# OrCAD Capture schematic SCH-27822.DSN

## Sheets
1 1. Title Page: title: FRDM-KL46Z; rev: B1; company: Freescale Semiconductor; note: SCH-27822 | PDF: SPF-27822; note: 6501 William Cannon Drive West; note: Austin, TX 78735-8598
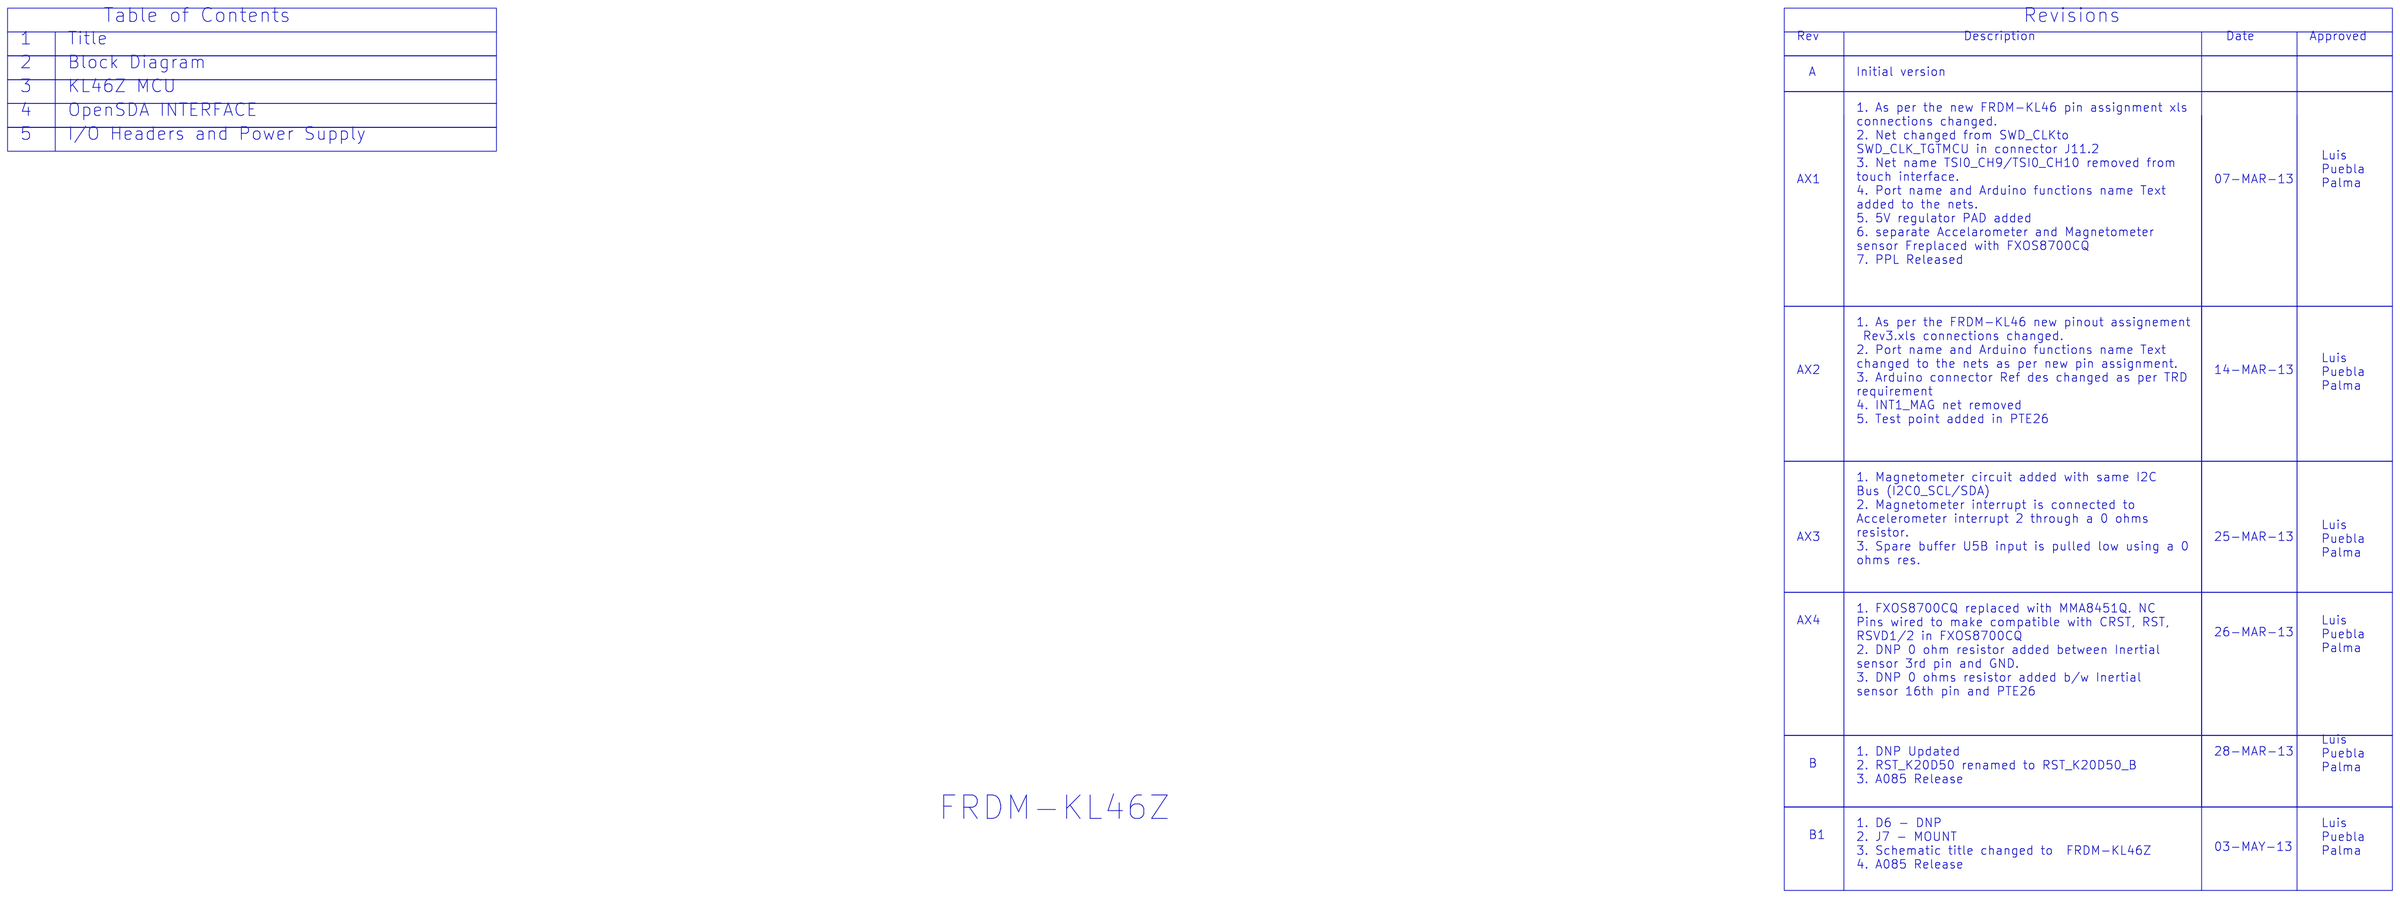
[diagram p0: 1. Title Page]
2 2. Block Diagram
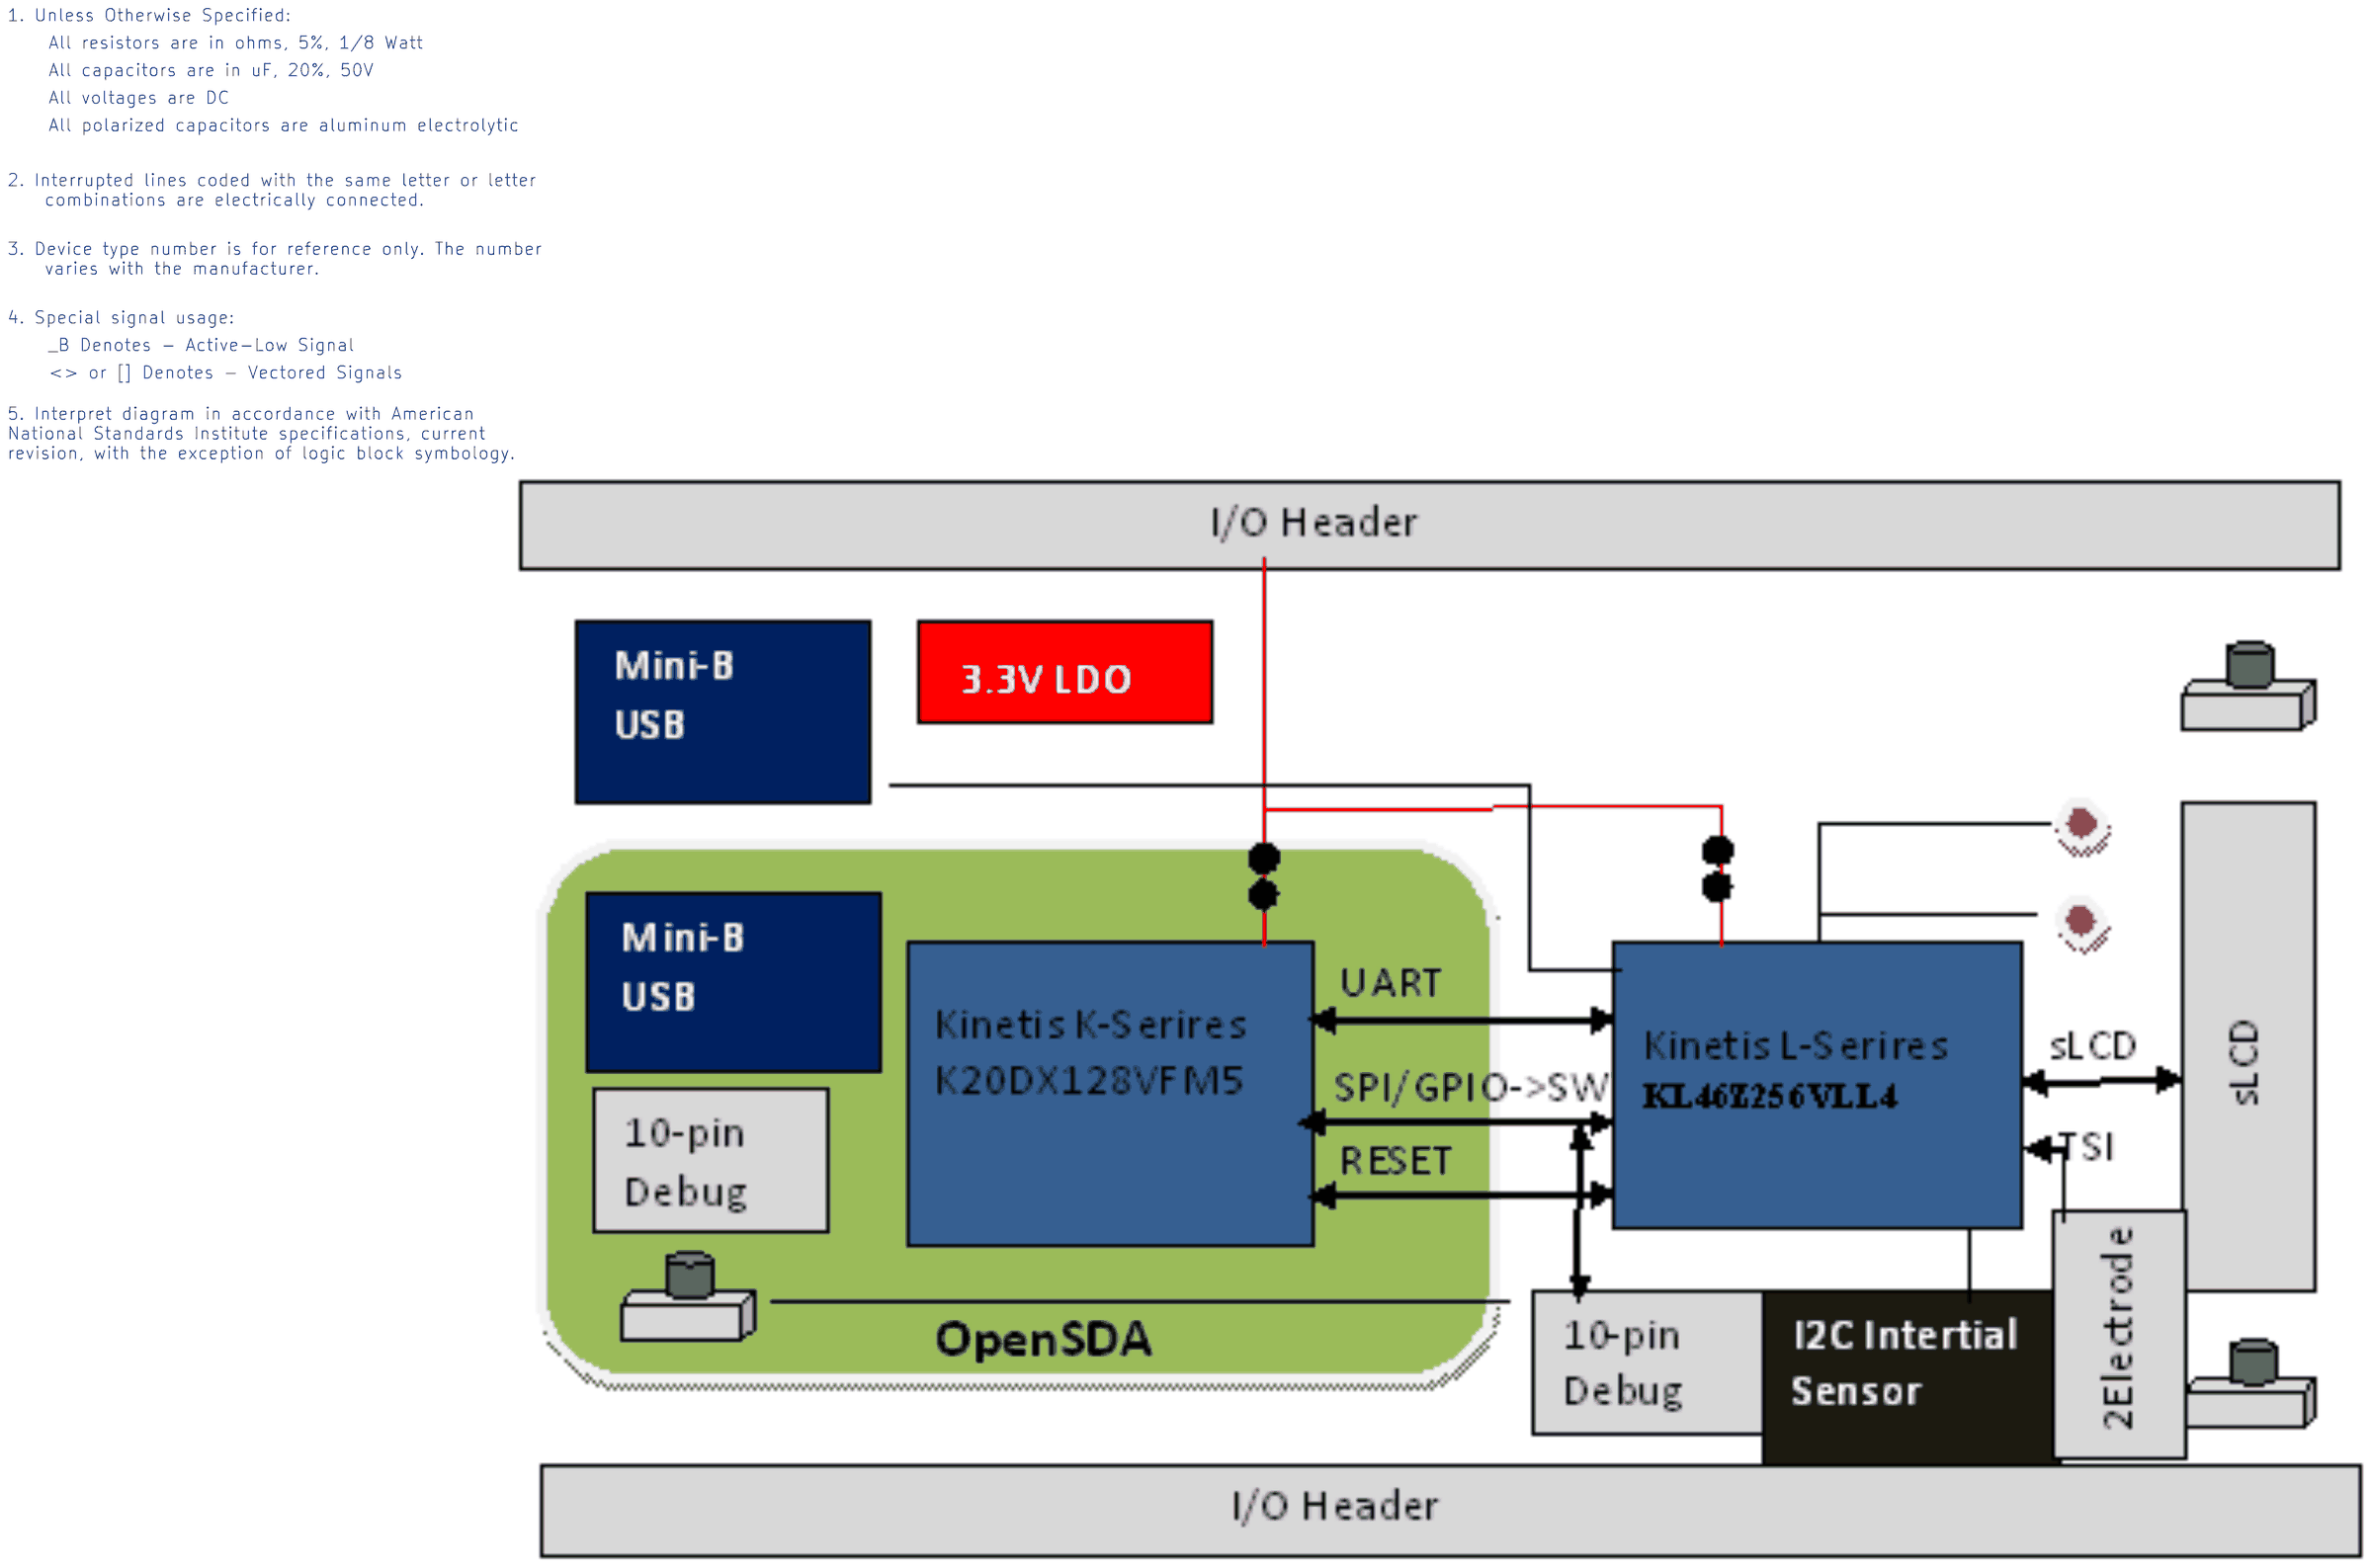
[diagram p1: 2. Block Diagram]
3 3. KL46Z MCU: size C
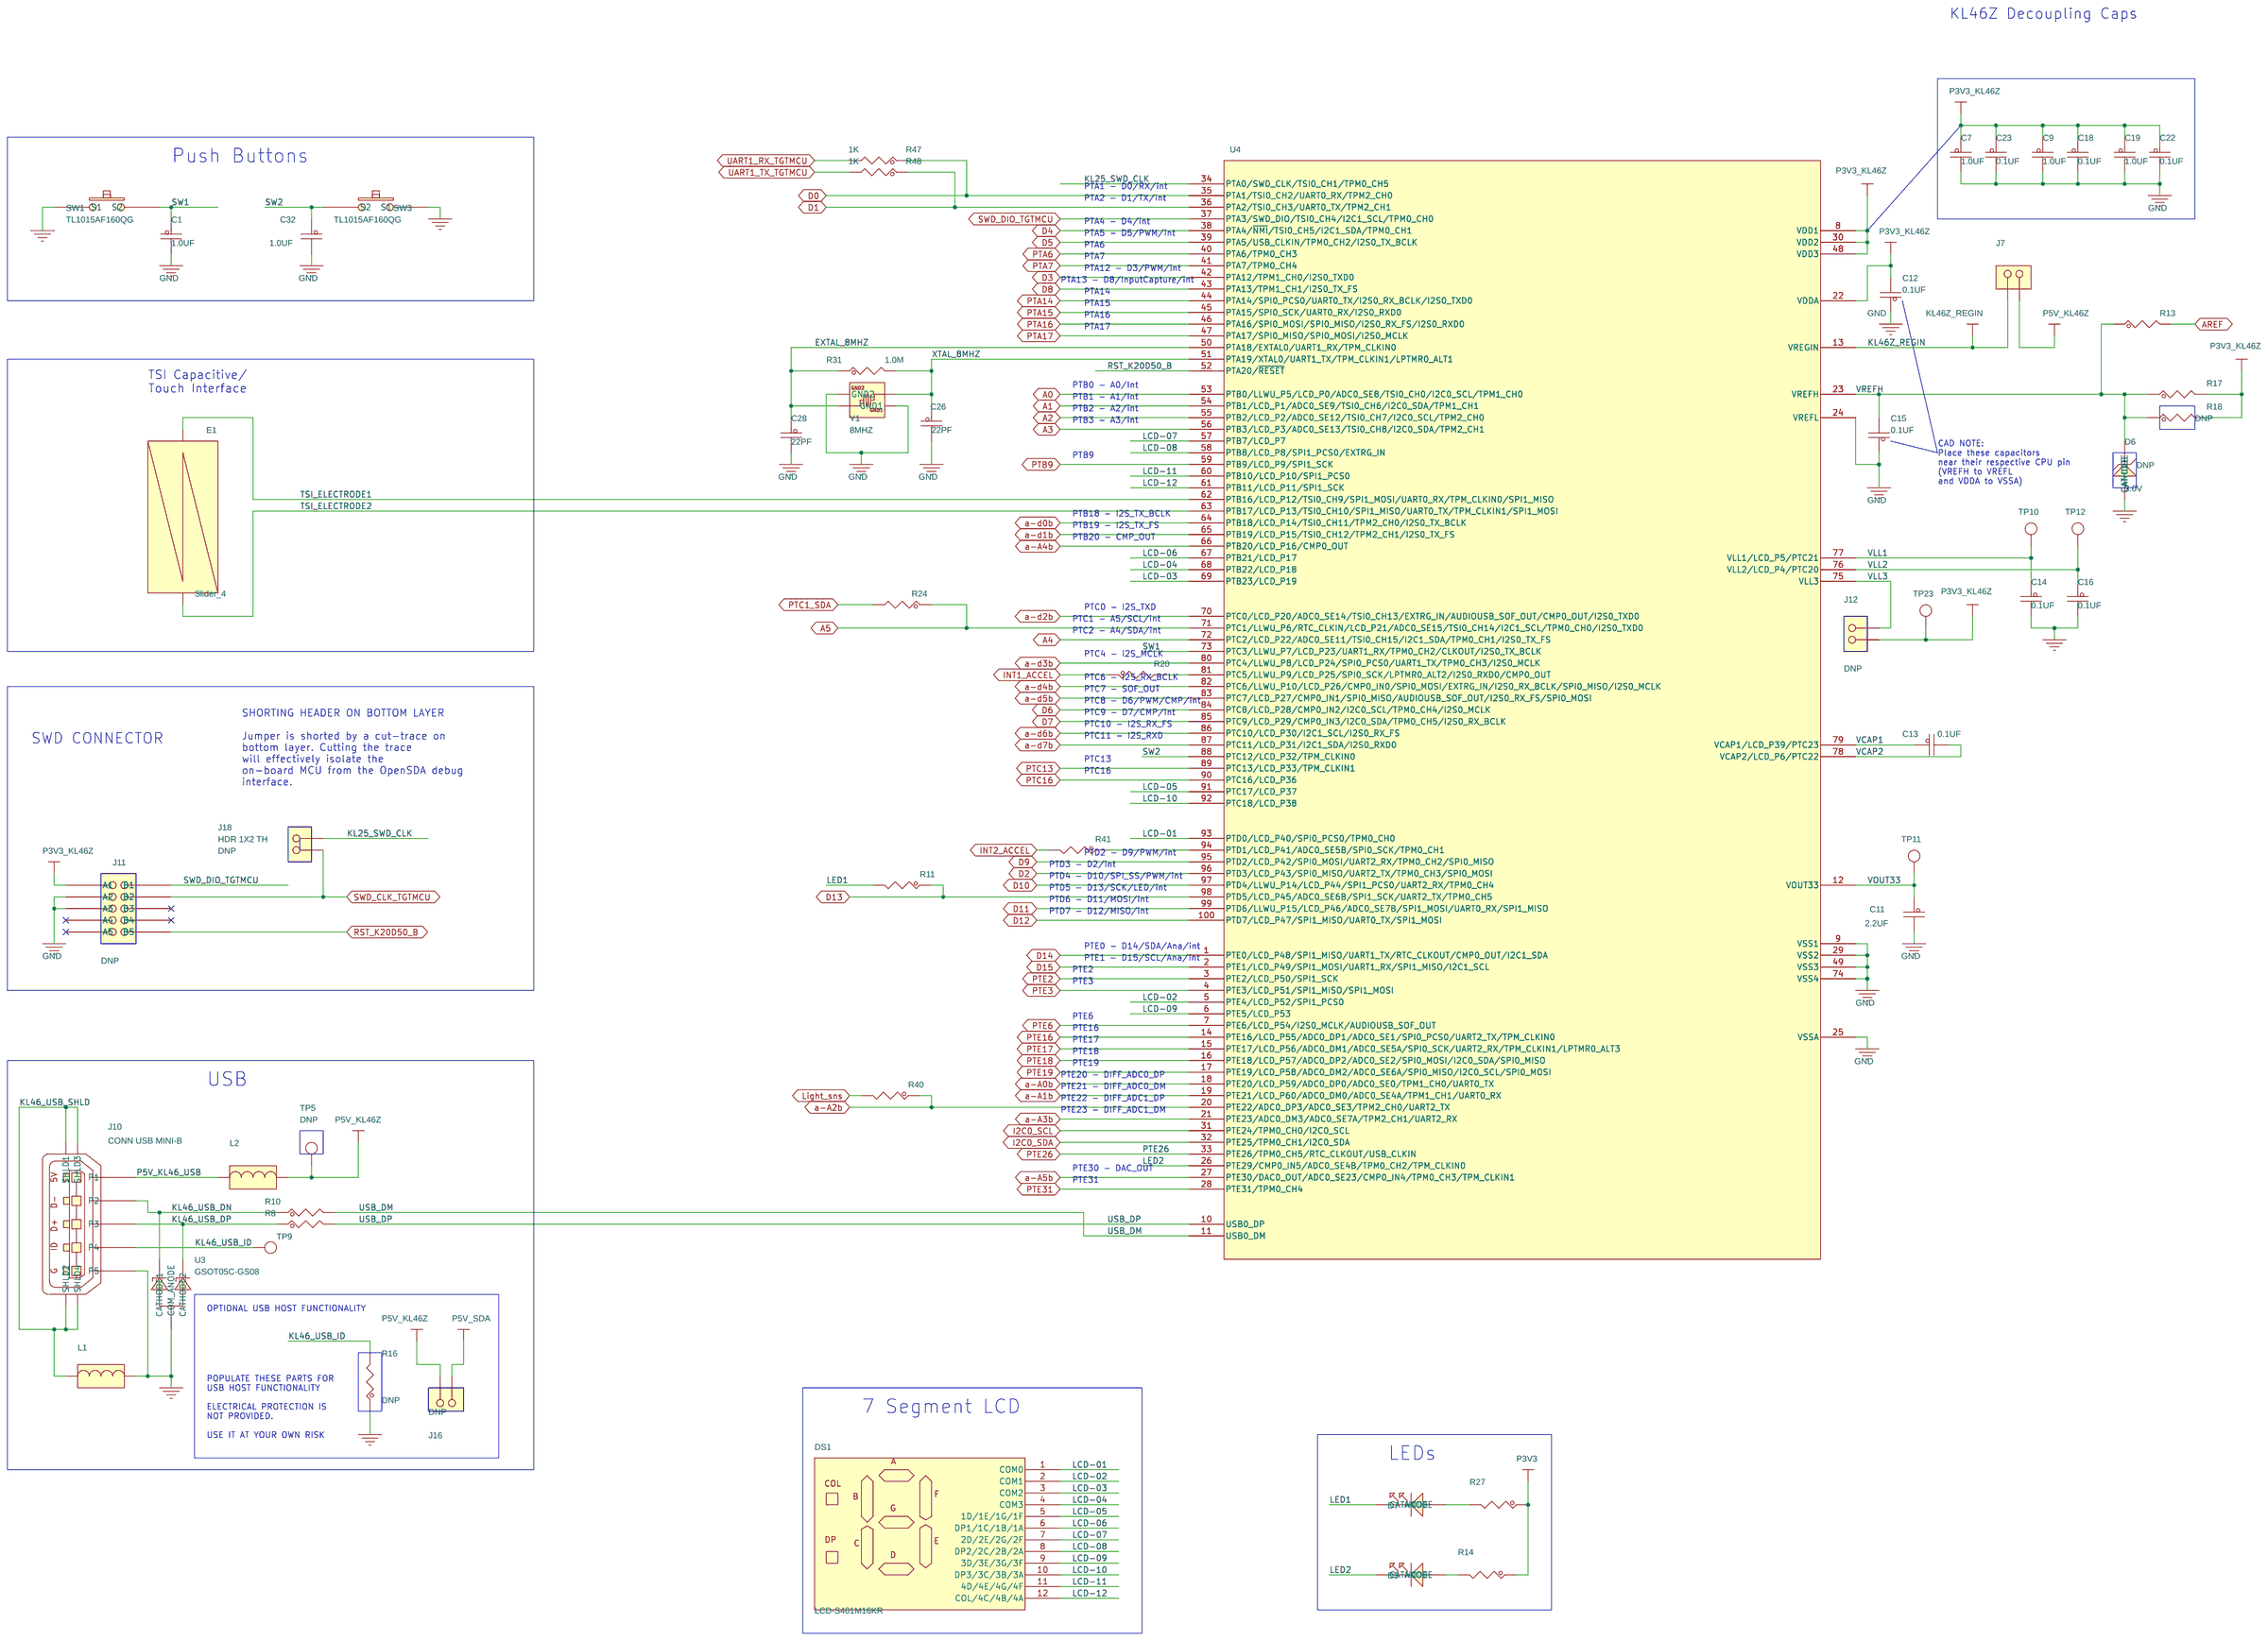
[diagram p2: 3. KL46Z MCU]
4 4. OpenSDA interface: size C
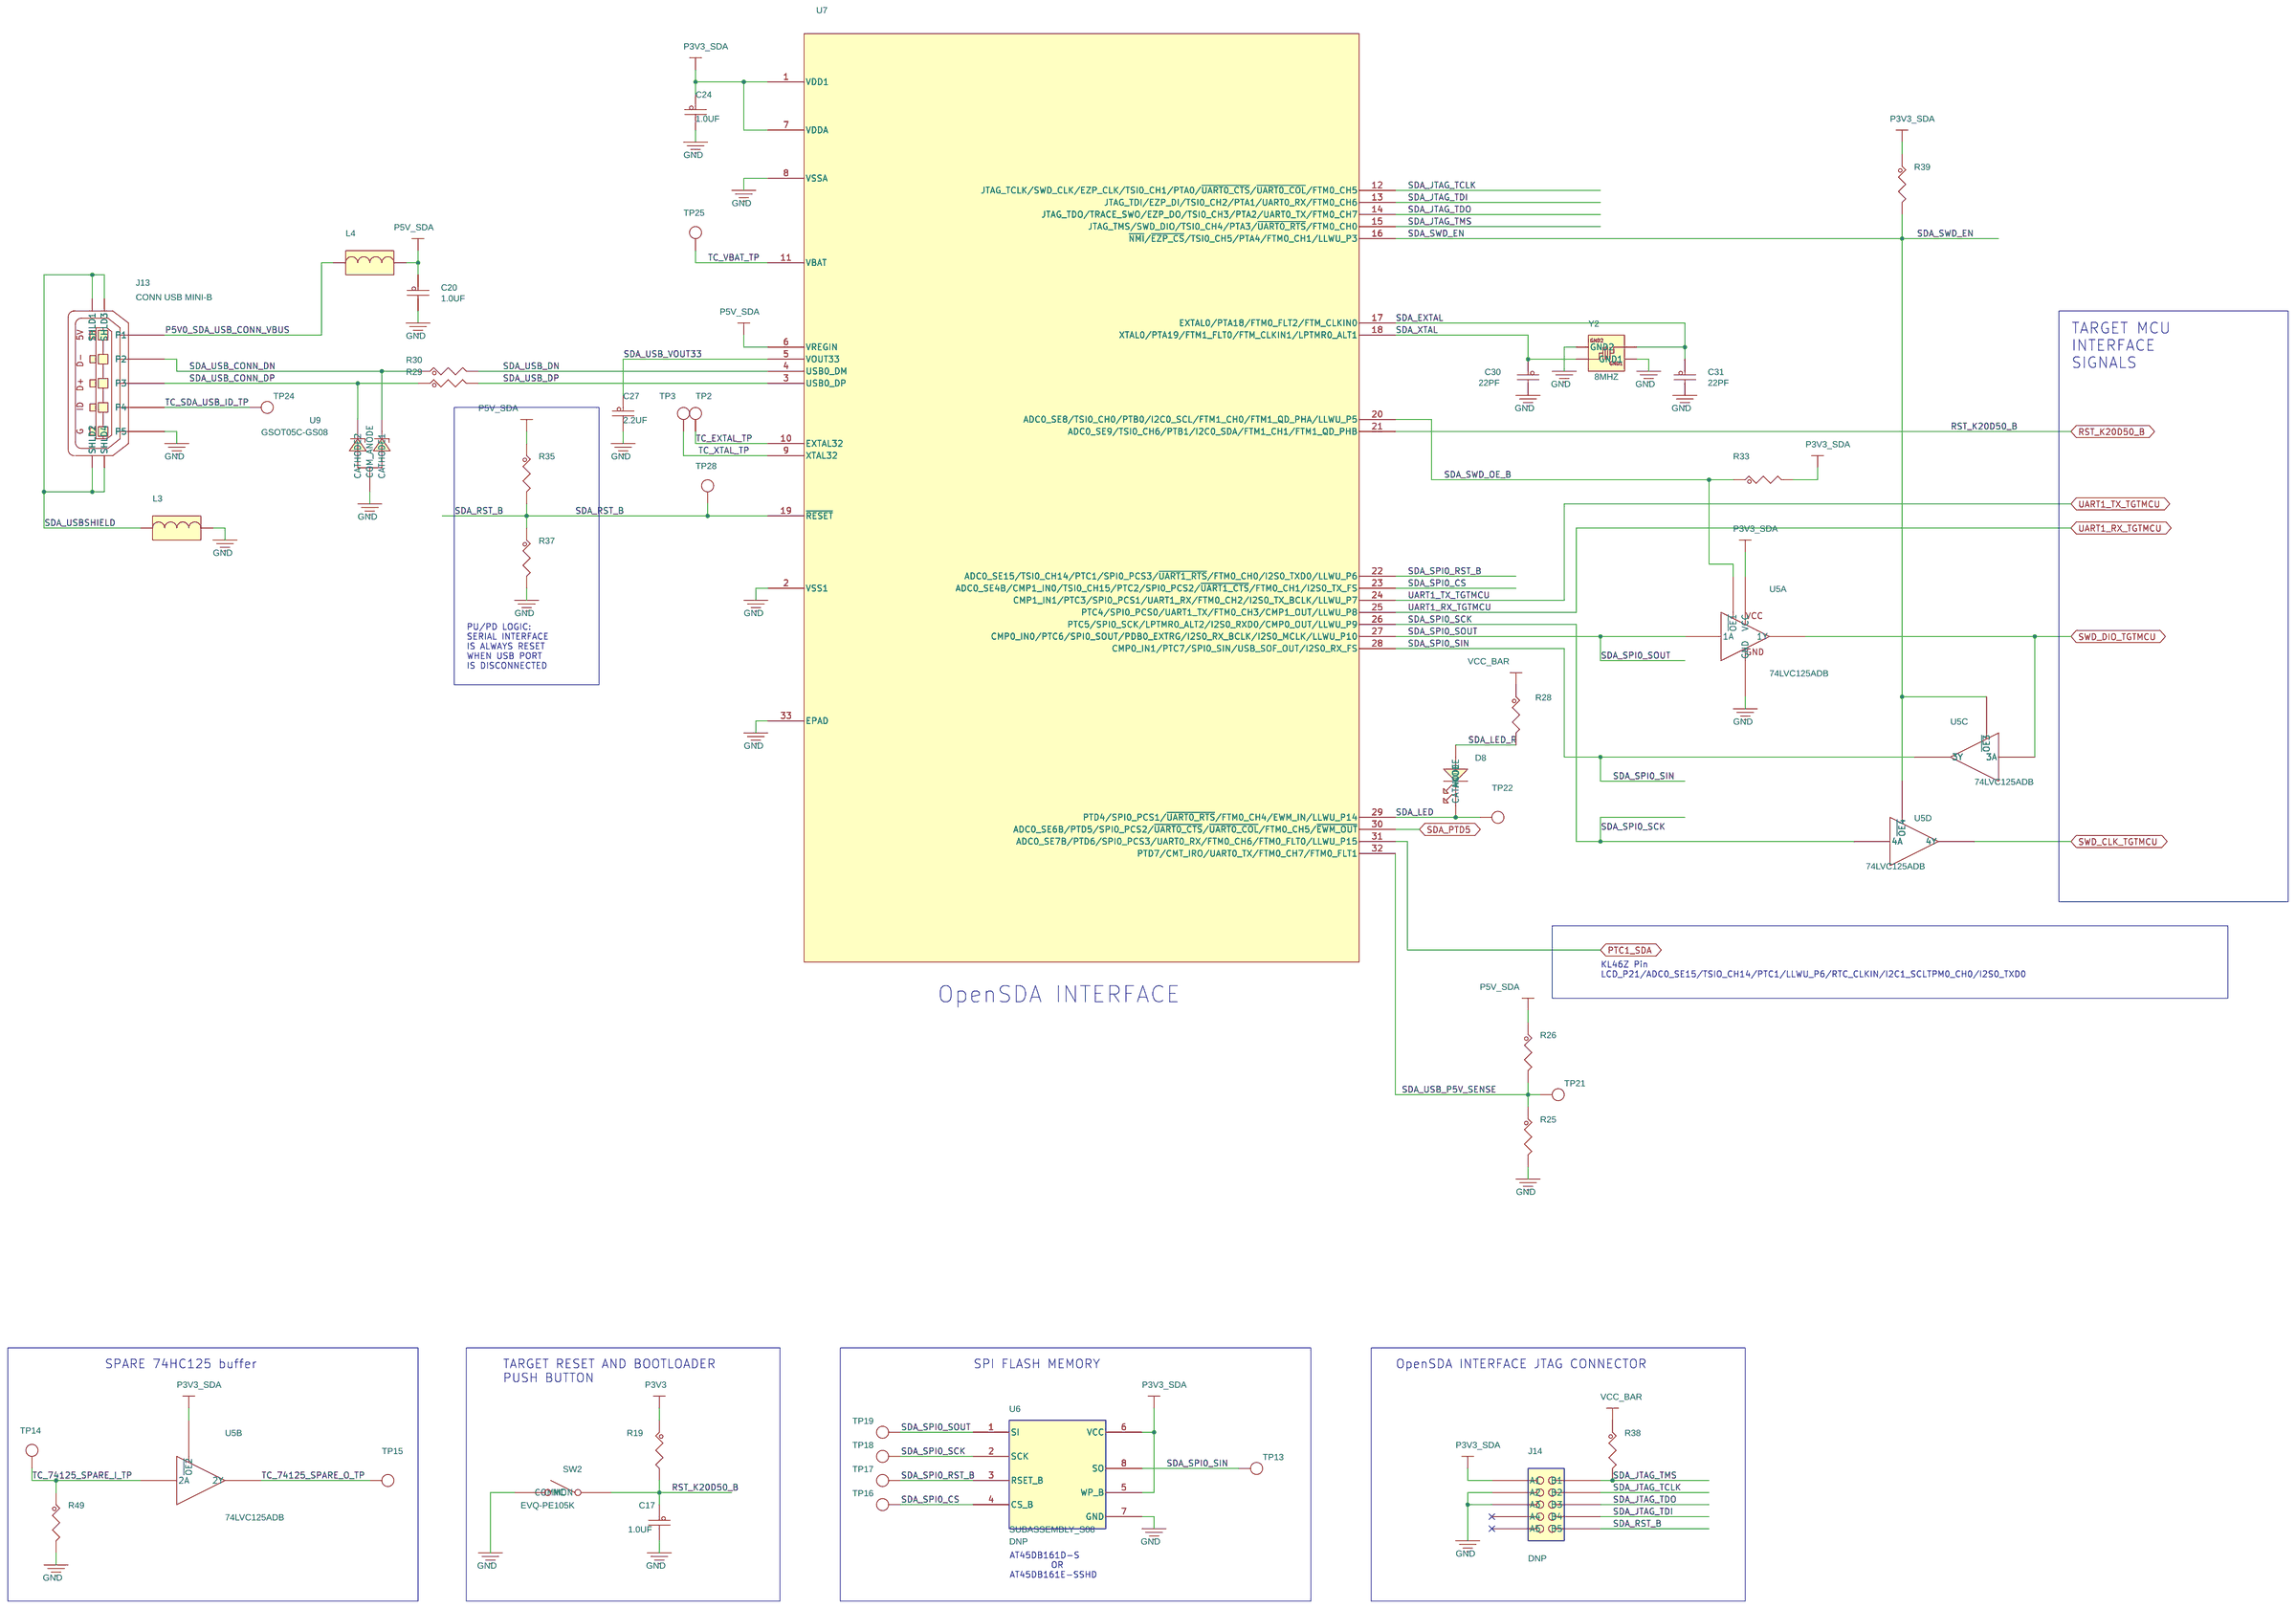
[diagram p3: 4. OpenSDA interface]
5 5. I/O Headers and Power Supply: size C
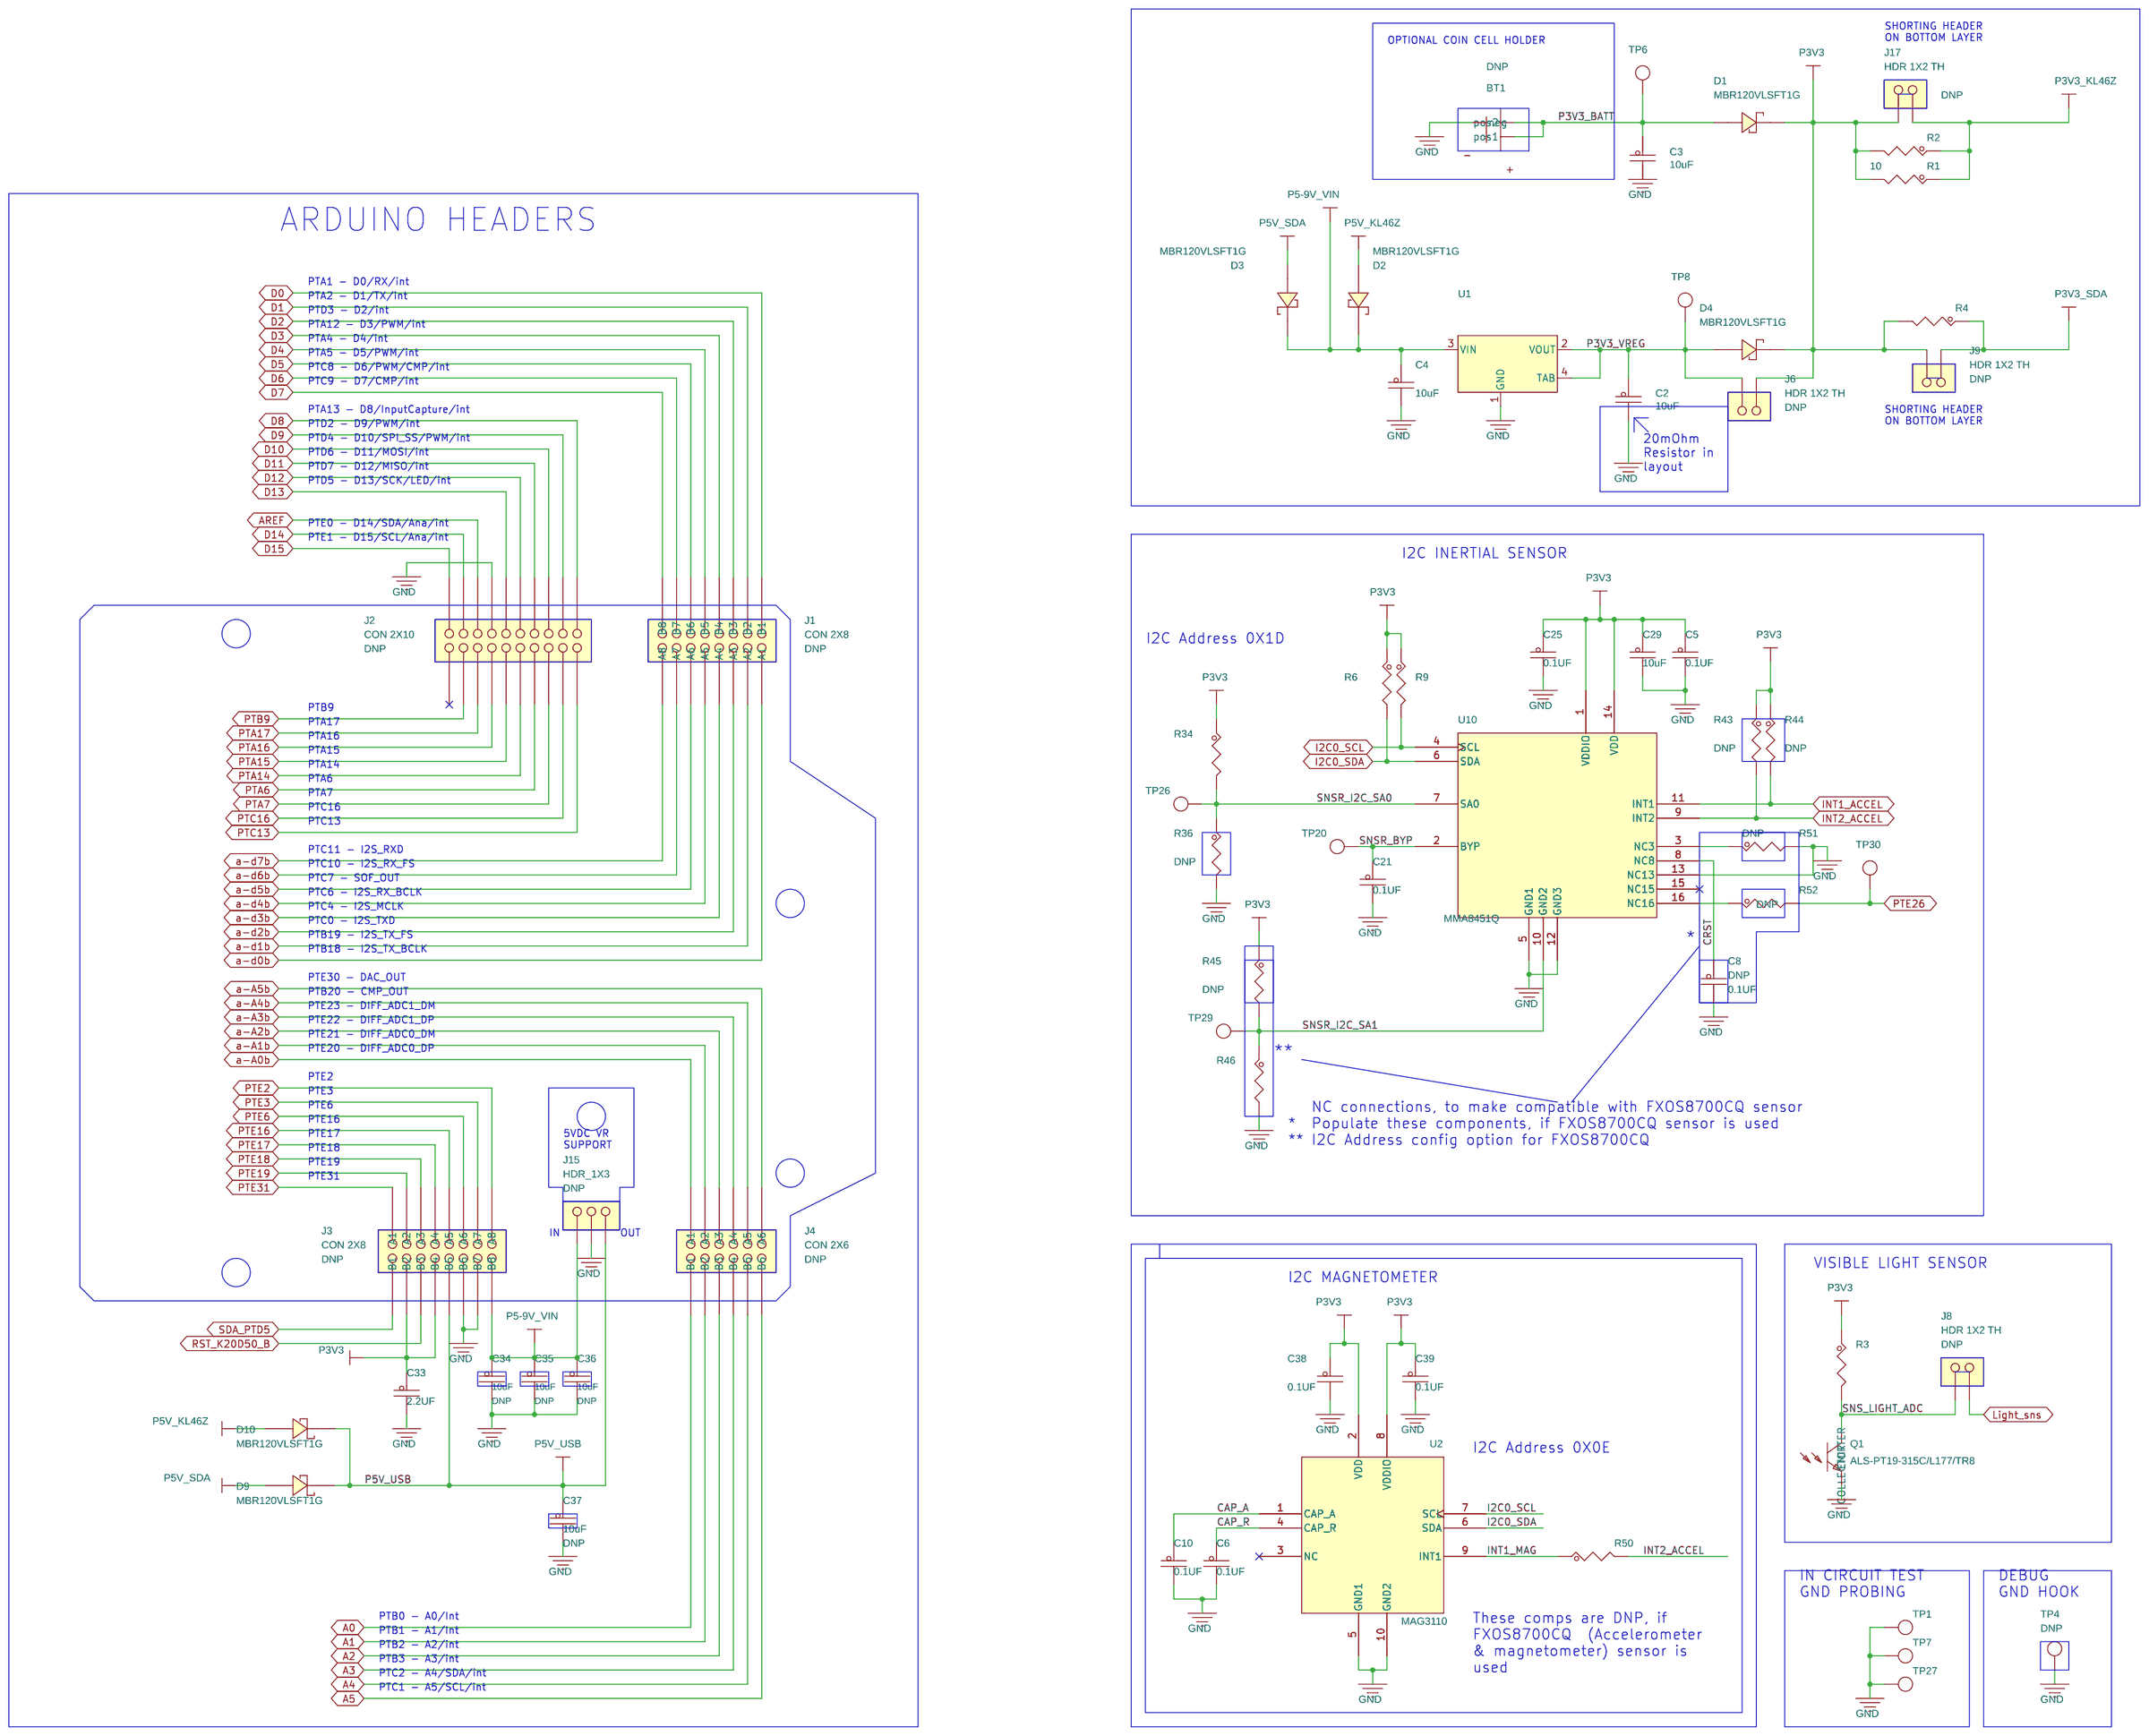
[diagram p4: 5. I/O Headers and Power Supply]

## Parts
sheet 3. KL46Z MCU
C1  1.0UF  [CC0402_25]
C7  1.0UF  [CC0402_25]
C9  1.0UF  [CC0402_25]
C11  2.2UF  [CC0603_OV]
C12  0.1UF  [CC0402_25]
C13  0.1UF  [CC0402_25]
C14  0.1UF  [CC0402_25]
C15  0.1UF  [CC0402_25]
C16  0.1UF  [CC0402_25]
C18  0.1UF  [CC0402_25]
C19  1.0UF  [CC0402_25]
C22  0.1UF  [CC0402_25]
C23  0.1UF  [CC0402_25]
C26  22PF  [CC0402_25]
C28  22PF  [CC0402_25]
C32  1.0UF  [CC0402_25]
D5  LED RED  [LED_0603]
D6  3.0V  [sod-323-A]
D7  LED GREEN  [LED_0603]
DS1  LCD-S401M16KR  [lcd12_1p5mm_20p32x10p16mm_th_nsp]
E1  Slider_4  [electrode_tri_4_12x38mm]
J7  HDR 1X2 TH  [HDR102]
J10  CONN USB MINI-B  [con5_usb_ra_smt]
J11  HDR 2X5  [hdr_5X2_ftsh_th_nsp]
J12  HDR 1X2 TH  [HDR102]
J16  HDR 1X2 TH  [HDR102]
J18  HDR 1X2 TH  [SH_HDR102_BOTTOM]
L1  330 OHM  [IND_0805]
L2  330 OHM  [IND_0805]
R8  33  [RC0402_25]
R10  33  [RC0402_25]
R11  0  [RC0603_OV]
R13  0  [RC0603_OV]
R14  330  [RC0402_25]
R16  0  [RC0603_OV]
R17  0  [RC0603_OV]
R18  1K  [RC0603_OV]
R20  0  [RC0603_OV]
R24  0  [RC0603_OV]
R27  330  [RC0402_25]
R31  1.0M  [RC0603_OV]
R40  0  [RC0603_OV]
R41  0  [RC0603_OV]
R47  1K  [RC0402_25]
R48  1K  [RC0402_25]
SW1  TL1015AF160QG  [sw2_spst_4x3_sm]
SW3  TL1015AF160QG  [sw2_spst_4x3_sm]
TP5  TEST POINT WHITE  [TEST_LOOP]
TP9  TPAD_030  [TPAD_030]
TP10  TPAD_040  [TPAD_040]
TP11  TP_PTH  [TP_PTH]
TP12  TPAD_040  [TPAD_040]
TP23  TPAD_040  [TPAD_040]
U3  GSOT05C-GS08  [sot23_a]
U4  MKL46Z256VLL4  [LQFP100_0P5_14X14]
Y1  8MHZ  [xtlosc4_5x3MM_sm]
sheet 4. OpenSDA interface
C17  1.0UF  [CC0402_25]
C20  1.0UF  [CC0402_25]
C24  1.0UF  [CC0402_25]
C27  2.2UF  [CC0603_OV]
C30  22PF  [CC0402_25]
C31  22PF  [CC0402_25]
D8  LED GREEN  [LED_0603]
J13  CONN USB MINI-B  [con5_usb_ra_smt]
J14  HDR 2X5  [hdr_5X2_ftsh_th_nsp]
L3  330 OHM  [IND_0805]
L4  330 OHM  [IND_0805]
R19  10K  [RC0603_OV]
R25  10K  [RC0603_OV]
R26  4.7K  [RC0603_OV]
R28  220  [RC0603_OV]
R29  33  [RC0402_25]
R30  33  [RC0402_25]
R33  10K  [RC0603_OV]
R35  4.7K  [RC0603_OV]
R37  10K  [RC0603_OV]
R38  10K  [RC0603_OV]
R39  10K  [RC0603_OV]
R49  0  [RC0603_OV]
SW2  EVQ-PE105K  [sw2_spst_3p5x6p0_5p0]
TP2  TP_PTH  [TP_PTH]
TP3  TP_PTH  [TP_PTH]
TP13  TPAD_030  [TPAD_030]
TP14  TPAD_030  [TPAD_030]
TP15  TPAD_030  [TPAD_030]
TP16  TPAD_030  [TPAD_030]
TP17  TPAD_030  [TPAD_030]
TP18  TPAD_030  [TPAD_030]
TP19  TPAD_030  [TPAD_030]
TP21  TPAD_030  [TPAD_030]
TP22  TPAD_030  [TPAD_030]
TP24  TPAD_030  [TPAD_030]
TP25  TPAD_030  [TPAD_030]
TP28  TPAD_030  [TPAD_030]
U5  74LVC125ADB  [ssop14]  (sections A,B,C,D)
U6  SUBASSEMBLY_S08  [SO8_DUAL_SOIC8S2_NSP]
U7  PK20DX128VFM5  [QFN32_S142EP]
U9  GSOT05C-GS08  [sot23_a]
Y2  8MHZ  [xtlosc4_5x3MM_sm]
sheet 5. I/O Headers and Power Supply
BT1  3003  [batt_21x20mm]
C2  10uF  [CC0603_OV]
C3  10uF  [CC0603_OV]
C4  10uF  [CC0603_OV]
C5  0.1UF  [CC0402_25]
C6  0.1UF  [CC0402_25]
C8  0.1UF  [CC0402_25]
C10  0.1UF  [CC0402_25]
C21  0.1UF  [CC0402_25]
C25  0.1UF  [CC0402_25]
C29  10uF  [CC0603_OV]
C33  2.2UF  [CC0603_OV]
C34  10uF  [CC0603_OV]
C35  10uF  [CC0603_OV]
C36  10uF  [CC0603_OV]
C37  10uF  [CC0603_OV]
C38  0.1UF  [CC0402_25]
C39  0.1UF  [CC0402_25]
D1  MBR120VLSFT1G  [SOD-123]
D2  MBR120VLSFT1G  [SOD-123]
D3  MBR120VLSFT1G  [SOD-123]
D4  MBR120VLSFT1G  [SOD-123]
D9  MBR120VLSFT1G  [SOD-123]
D10  MBR120VLSFT1G  [SOD-123]
J1  CON 2X8  [hdr_2x8_2p54_th_nsp]
J2  CON 2X10  [hdr_2x10_2p54_th_nsp]
J3  CON 2X8  [hdr_2x8_2p54_th_nsp]
J4  CON 2X6  [hdr_2x6_2p54_th_nsp]
J6  HDR 1X2 TH  [SH_HDR102_BOTTOM]
J8  HDR 1X2 TH  [SH_HDR102_BOTTOM]
J9  HDR 1X2 TH  [SH_HDR102_BOTTOM]
J15  HDR_1X3  [HDR103]
J17  HDR 1X2 TH  [SH_HDR102_BOTTOM]
Q1  ALS-PT19-315C/L177/TR8  [phtrans_1p9x1]
R1  10  [RC0603_OV]
R2  0  [RC0603_OV]
R3  10K  [RC0603_OV]
R4  0  [RC0603_OV]
R6  4.7K  [RC0603_OV]
R9  4.7K  [RC0603_OV]
R34  10K  [RC0603_OV]
R36  10K  [RC0603_OV]
R43  10K  [RC0603_OV]
R44  10K  [RC0603_OV]
R45  10K  [RC0603_OV]
R46  0  [RC0603_OV]
R50  0  [RC0603_OV]
R51  0  [RC0603_OV]
R52  0  [RC0603_OV]
TP1  TPAD_030  [TPAD_030]
TP4  TEST POINT WHITE  [TEST_LOOP]
TP6  TPAD_030  [TPAD_030]
TP7  TPAD_030  [TPAD_030]
TP8  TPAD_030  [TPAD_030]
TP20  TPAD_030  [TPAD_030]
TP26  TPAD_030  [TPAD_030]
TP27  TPAD_030  [TPAD_030]
TP29  TPAD_030  [TPAD_030]
TP30  TP_PTH  [TP_PTH]
U1  NCP1117ST33T3G  [sot223]
U2  MAG3110  [DFN_10_0P4_2X2_B]
U10  MMA8451Q  [QFN5X3_0P5_3X3]

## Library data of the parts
C1 C7 C9 C17 C19 C20 C24 C32 = CAP_NP: CAP CER 1.0UF 10V 10% X5R 0402; AGILE_PN: 150-75772; CAD_APPROVED: Yes; FPLIST: CC0402_25,CC0402_HD,0402_CC; HEIGHT: 0.6MM; MFG_NAME01: YAGEO AMERICA; MFG_PN01: CC0402KRX5R6BB105; ROHS: Yes; VOLTAGE: 10V
C11 C27 C33 = CAP_NP: CAP CER 2.2UF 10V 10% X7R 0603; AGILE_PN: 150-78564; CAD_APPROVED: Yes; FPLIST: CC0603_OV,CC0603,0603_CC; HEIGHT: 1.25MM; MFG_NAME01: TAIYO YUDEN; MFG_PN01: LMK107B7225KA-T; ROHS: Yes; Tolerance: 10%; VOLTAGE: 10V
C5 C6 C10 C12 C15 C18 C21-C23 C25 C38 C39 = CAP_NP: CAP CER 0.1UF 10V 10% X5R 0402; AGILE_PN: 150-75634; CAD_APPROVED: Yes; FPLIST: CC0402_25,CC0402_HD,0402_CC; HEIGHT: 0.64MM; MFG_NAME01: KEMET; MFG_PN01: C0402C104K8PAC; ROHS: Yes; Tolerance: 10%; VOLTAGE: 10V
C13 C14 C16 = CAP_NP: CAP CER 0.1UF 10V 10% X5R 0402; AGILE_PN: 150-75634; CAD_APPROVED: Yes; FPLIST: CC0402_25,CC0402_HD,0402_CC; HEIGHT: 0.64MM; MFG_NAME01: KEMET; MFG_PN01: C0402C104K8PAC; ROHS: Yes; TOL: 10%; Tolerance: 10%; VOLTAGE: 10V
C26 C28 C30 C31 = CAP_NP: CAP CER 22PF 50V 5% C0G 0402; AGILE_PN: 150-75266; CAD_APPROVED: Yes; FPLIST: CC0402_25,CC0402_HD,0402_CC; HEIGHT: 0.635MM; MFG_NAME01: AVX; MFG_PN01: 04025A220JAT2A; ROHS: Yes; Tolerance: 5%; VOLTAGE: 50V
D5 = LED: LED RED SGL 1.7V 25MA 0603; AGILE_PN: 370-75083; CAD_APPROVED: Yes; HEIGHT: 0.8mm; MFG_NAME01: DIALIGHT; MFG_PN01: 597-5112-407F; ROHS: Yes
D6 = ZDIODE: DIODE ZNR -- 3V 200MW SOD323; AGILE_PN: 480-78396; ASSY_OPT: DNP; CAD_APPROVED: Yes; HEIGHT: 1.1MM; MFG_NAME01: ON SEMICONDUCTOR; MFG_PN01: MM3Z3V0T1G; ROHS: Yes
D7 D8 = LED: LED GRN SGL 20MA 0603; AGILE_PN: 370-76565; CAD_APPROVED: Yes; HEIGHT: 0.67MM; MFG_NAME01: osram; MFG_PN01: LG L29K-G2J1-24-Z; ROHS: Yes
DS1 = LCD_S401M16KR_12P: LCD DISPLAY 7-SEG 0.17" 3.3V TH; AGILE_PN: 336-76578; CAD_APPROVED: Yes; HEIGHT: 2.8MM; MFG_NAME01: LUMEX
E1 = ELECTRODE_TRI_2: ELECTRODE SLIDER 4 TRIANGLE, NO PART TO ORDER; AGILE_PN: 510-77835; CAD_APPROVED: Yes; HEIGHT: 0.127MM; MFG_NAME01: NO PART TO ORDER; MFG_PN01: NO PART TO ORDER; ROHS: Yes
J7 = CONN_HDR_2X1: HDR 1X2 TH 100MIL SP 339H AU 98L; AGILE_PN: 210-75439; CAD_APPROVED: YES; HEIGHT: 8.71 MM; MFG_NAME01: SAMTEC; MFG_PN01: TSW-102-07-G-S; ROHS: Yes
J10 J13 = USB_MINI_AB_RECEPTACLE: CON 5 USB_MINI_B_RECEPTACLE RA SMT 0.8MM 168H AU; AGILE_PN: 211-79254; CAD_APPROVED: Yes; HEIGHT: 4.27MM; MFG_NAME01: TE Connectivity Ltd; MFG_PN01: 1734035-2; ROHS: Yes
J11 J14 = CONN_HDR_5X2: HDR 2X5 TH 50MIL CTR 167H AU 91L; AGILE_PN: 210-80192; ASSY_OPT: DNP; CAD_APPROVED: Yes; FPLIST: hdr_5X2_ftsh_th,hdr_5X2_ftsh_th_nsp; HEIGHT: 4.25MM; MFG_NAME01: ANYTRONIC CORPORATION LIMITED; MFG_PN01: 0922S0205011N6T-2LF; ROHS: Yes
J12 J16 = CONN_HDR_2X1: HDR 1X2 TH 100MIL SP 339H AU 98L; AGILE_PN: 210-75439; ASSY_OPT: DNP; CAD_APPROVED: YES; HEIGHT: 8.71 MM; MFG_NAME01: SAMTEC; MFG_PN01: TSW-102-07-G-S; ROHS: Yes
J6 J8 J9 J17 J18 = CONN_HDR_2X1: HDR 1X2 TH 100MIL SP 339H AU 98L; AGILE_PN: 210-75439; ASSY_OPT: DNP; CAD_APPROVED: YES; FPLIST: HDR102,SH_HDR102_BOTTOM; HEIGHT: 8.71 MM; MFG_NAME01: SAMTEC; MFG_PN01: TSW-102-07-G-S; ROHS: Yes
L1 L2 = BEAD: IND FER BEAD 330OHM@100MHZ 2.5A -- SMT; AGILE_PN: 180-30021; CAD_APPROVED: YES; HEIGHT: 1.05 MM; MFG_NAME01: TDK; MFG_PN01: MPZ2012S331A; PART_TYPE: FERRITE; ROHS: Yes; TOL: 25%; Tolerance: 25%
R8 R10 R29 R30 = RES: RES MF 33.0 OHM 1/16W 1% 0402; AGILE_PN: 470-75790; CAD_APPROVED: Yes; FPLIST: RC0402_25,RC0402_HD,RC0402_X2,0402_CC; MFG_NAME01: THYE MING TECH CO LTD; MFG_PN01: CR-02FL6---33R; ROHS: Yes; Tolerance: 1%
R2 R4 R11 R13 R17 R20 R24 R40 R41 = RES: RES MF ZERO OHM 1/10W -- 0603; AGILE_PN: 470-75407; CAD_APPROVED: Yes; FPLIST: RC0603_OV,RC0603,R603-X2,0603_CC; MFG_NAME01: VISHAY INTERTECHNOLOGY; MFG_PN01: CRCW06030000Z0EA; ROHS: Yes; Tolerance: 1%
R14 R27 = RES: RES MF 330 OHM 1/16W 1% AEC-Q200 0402; AGILE_PN: 470-76465; CAD_APPROVED: Yes; FPLIST: RC0402_25,RC0402_HD,0402_CC; HEIGHT: 0.4MM; MFG_NAME01: VISHAY INTERTECHNOLOGY; MFG_PN01: CRCW0402330RFK; ROHS: Yes; TOL: 1%; Tolerance: 1%
R16 = RES: RES MF ZERO OHM 1/10W -- 0603; AGILE_PN: 470-75407; ASSY_OPT: DNP; CAD_APPROVED: Yes; FPLIST: RC0603_OV,RC0603,R603-X2,0603_CC; MFG_NAME01: VISHAY INTERTECHNOLOGY; MFG_PN01: CRCW06030000Z0EA; ROHS: Yes; Tolerance: 1%
R18 = RES: RES MF 1.0K 1/10W 5% 0603; AGILE_PN: 470-75412; ASSY_OPT: DNP; CAD_APPROVED: YES; FPLIST: RC0603_OV,RC0603,0603_CC; MFG_NAME01: VENKEL COMPANY; MFG_PN01: CR0603-10W-102JT; ROHS: Yes; Tolerance: 5%
R31 = RES: RES MF 1.0M 1/10W 5% 0603; AGILE_PN: 470-75846; CAD_APPROVED: Yes; FPLIST: RC0603_OV,RC0603,0603_CC; MFG_NAME01: BOURNS; MFG_PN01: CR0603-JW-105ELF; ROHS: Yes; Tolerance: 5%
R47 R48 = RES: RES MF 1.0K 1/16W 5% 0402; AGILE_PN: 470-75555; CAD_APPROVED: Yes; FPLIST: RC0402_25,RC0402_HD,RC0402_X2,0402_CC; MFG_NAME01: VISHAY INTERTECHNOLOGY; MFG_PN01: CRCW04021K00JNED; ROHS: Yes; Tolerance: 5%
SW1 SW3 = SW_SPNO_2P: SW SPST PB 50MA 12V SMT; AGILE_PN: 510-77720; CAD_APPROVED: Yes; HEIGHT: 2.25MM; MFG_NAME01: E SWITCH; ROHS: Yes
TP4 TP5 = TestLoop: TEST POINT WHITE 40 MIL DRILL 180 MIL TH 109L; AGILE_PN: 210-75685; ASSY_OPT: DNP; CAD_APPROVED: Yes; HEIGHT: 4.8 MM; MFG_NAME01: COMPONENTS CORPORATION; MFG_PN01: TP-105-01-09; ROHS: Yes
TP1 TP6-TP9 TP20-TP22 TP26-TP29 = TestLoop: TEST POINT PAD 30MIL DIA SMT, NO PART TO ORDER; AGILE_PN: 211-76642; CAD_APPROVED: Yes; HEIGHT: 0.1MM; MFG_NAME01: NOTACOMPONENT; MFG_PN01: NOTACOMPONENT; ROHS: Yes
TP10 TP12 TP23 = TestLoop: TEST POINT PAD 40MIL DIA SMT, NO PART TO ORDER; AGILE_PN: 211-76643; CAD_APPROVED: Yes; HEIGHT: 0.1MM; MFG_NAME01: NOTACOMPONENT; MFG_PN01: NOTACOMPONENT; ROHS: Yes
TP2 TP3 TP11 TP30 = TestLoop: TEST POINT PAD 035-018MIL TH, NO PART TO ORDER; AGILE_PN: 210-77612; CAD_APPROVED: Yes; HEIGHT: 0.1 mm; MFG_NAME01: NOTACOMPONENT; MFG_PN01: NOTACOMPONENT; ROHS: Yes
U3 U9 = DIODE_2LINE_ESD: DIODE ESD 2LINE 5V SOT23; AGILE_PN: 480-78313; CAD_APPROVED: Yes; HEIGHT: 1.15MM; MFG_NAME01: VISHAY INTERTECHNOLOGY; ROHS: Yes
U4 = PKL46Z_LQFP100: IC MCU 256KB FLASH 48MHZ 1.71-3.6V LQFP100; AGILE_PN: 344-01470; CAD_APPROVED: Yes; HEIGHT: 1.7MM; MFG_NAME01: FREESCALE SEMICONDUCTOR; ROHS: Yes
Y1 Y2 = CRYSTAL_JXS63: XTAL 8MHZ 20PPM PAR 18PF ESR 200OHM SMT; AGILE_PN: 230-77754; CAD_APPROVED: Yes; HEIGHT: 1.1MM; MFG_NAME01: Abracon Corporation; MFG_PN01: ABM3B-8.000MHZ-B2-T; ROHS: Yes
L3 L4 = BEAD: IND FER BEAD 330OHM@100MHZ 2.5A -- SMT; AGILE_PN: 180-30021; CAD_APPROVED: YES; HEIGHT: 1.05 MM; MFG_NAME01: TDK; MFG_PN01: MPZ2012S331A; PART_TYPE: FERRITE; ROHS: Yes; Tolerance: 25%
R3 R19 R25 R33 R34 R37-R39 = RES: RES MF 10K 1/10W 5% 0603; AGILE_PN: 470-75410; CAD_APPROVED: Yes; FPLIST: RC0603_OV,RC0603,0603_CC; MFG_NAME01: KOA SPEER; MFG_PN01: RK73B1JTTD103J; ROHS: Yes; Tolerance: 5%
R6 R9 R26 R35 = RES: RES MF 4.7K 1/10W 5% 0603; AGILE_PN: 470-75414; CAD_APPROVED: Yes; FPLIST: RC0603_OV,RC0603,0603_CC; MFG_NAME01: VISHAY INTERTECHNOLOGY; MFG_PN01: CRCW06034K70JNEA; ROHS: Yes; Tolerance: 5%
R28 = RES: RES MF 220 OHM 1/10W 5% 0603; AGILE_PN: 470-30297; CAD_APPROVED: Yes; FPLIST: RC0603_OV,RC0603,0603_CC; MFG_NAME01: KOA SPEER; MFG_PN01: RK73B1JTTD221J; ROHS: Yes; Tolerance: 5%
R46 R49 R50 = RES: RES MF ZERO OHM 1/10W -- 0603; AGILE_PN: 470-75407; CAD_APPROVED: Yes; FPLIST: RC0603_OV,RC0603,0603_CC; MFG_NAME01: VISHAY INTERTECHNOLOGY; MFG_PN01: CRCW06030000Z0EA; ROHS: Yes; Tolerance: 1%
SW2 = SW2P: SW SPST NO 0.05A 12V SMD; AGILE_PN: 510-77858; CAD_APPROVED: Yes; HEIGHT: 5.2 MM; MFG_NAME01: PANASONIC; MFG_PN01: EVQPE105K; ROHS: Yes
TP13-TP19 TP24 TP25 = TESTLOOP: TEST POINT PAD 30MIL DIA SMT, NO PART TO ORDER; AGILE_PN: 211-76642; CAD_APPROVED: Yes; HEIGHT: 0.1MM; MFG_NAME01: NOTACOMPONENT; MFG_PN01: NOTACOMPONENT; ROHS: Yes
U5 = 74-125_14P: IC BUF QUAD TS 1.2-3.6V SSOP14; AGILE_PN: 312-79933; CAD_APPROVED: Yes; HEIGHT: 2mm; MFG_NAME01: NXP SEMICONDUCTORS; ROHS: Yes
U6 = AT45DB161D-S: SUBASSEMBLY IC FLASH 16MBIT 2.5-3.6V SOIC8 + IC FLASH 16MBIT 85MHZ 2.5-3.6V SOIC8; AGILE_PN: 750-77350; ASSY_OPT: DNP; CAD_APPROVED: Yes; HEIGHT: 2.16 MM; MFG_NAME01: SUBASSEMBLY; MFG_PN01: 342-00456,342-00525; ROHS: Yes
U7 = PK20DX128V_QFN_32P: IC MCU FLASH 128KB 50MHZ 1.71-3.6V QFN32; AGILE_PN: 344-01231; CAD_APPROVED: Yes; HEIGHT: 1MM; MFG_NAME01: FREESCALE SEMICONDUCTOR; MFG_PN01: MK20DX128VFM5; ROHS: Yes
BT1 = BATTERY_SKT_3V: HOLDER BATTERY 20MM DIA TH; AGILE_PN: 801-76130; ASSY_OPT: DNP; CAD_APPROVED: Yes; HEIGHT: 4.21MM; MFG_NAME01: Keystone Electronics; ROHS: Yes
C2-C4 C29 = CAP_NP: CAP CER 10UF 10V 20% X5R 0603; AGILE_PN: 150-78609; CAD_APPROVED: Yes; FPLIST: CC0603_OV,CC0603,0603_CC; HEIGHT: 1.016MM; MFG_NAME01: TAIYO YUDEN; MFG_PN01: LMK107BJ106MALTD; ROHS: Yes; VOLTAGE: 10V
C8 = CAP_NP: CAP CER 0.1UF 10V 10% X5R 0402; AGILE_PN: 150-75634; ASSY_OPT: DNP; CAD_APPROVED: Yes; FPLIST: CC0402_25,CC0402_HD,0402_CC; HEIGHT: 0.64MM; MFG_NAME01: KEMET; MFG_PN01: C0402C104K8PAC; ROHS: Yes; Tolerance: 10%; VOLTAGE: 10V
C34-C37 = CAP_NP: CAP CER 10UF 10V 20% X5R 0603; AGILE_PN: 150-78609; ASSY_OPT: DNP; CAD_APPROVED: Yes; FPLIST: CC0603_OV,CC0603,0603_CC; HEIGHT: 1.016MM; MFG_NAME01: TAIYO YUDEN; MFG_PN01: LMK107BJ106MALTD; ROHS: Yes; VOLTAGE: 10V
D1-D4 D9 D10 = DIODE_SCHTKY: DIODE SCH RECT 1A 20V SMT; AGILE_PN: 480-75997; CAD_APPROVED: Yes; HEIGHT: 1MM; MFG_NAME01: ON SEMICONDUCTOR; ROHS: Yes
J1 J3 = CONN_HDR_8X2: CON 2X8 SKT TH 100MIL CTR 345H AU 126L; AGILE_PN: 210-80190; ASSY_OPT: DNP; CAD_APPROVED: Yes; FPLIST: hdr_2x8_2p54_th,hdr_2x8_2p54_th_nsp; HEIGHT: 8.75MM; MFG_NAME01: ANYTRONIC CORPORATION LIMITED; MFG_PN01: 08010S31611-24LF; ROHS: Yes
J2 = CONN_HDR_10X2: CON 2X10 SKT TH 100MIL CTR 345H AU 126L; AGILE_PN: 210-80191; ASSY_OPT: DNP; CAD_APPROVED: Yes; FPLIST: hdr_2x10_2p54_th,hdr_2x10_2p54_th_nsp; HEIGHT: 8.75MM; MFG_NAME01: ANYTRONIC CORPORATION LIMITED; MFG_PN01: 08010S32011-24LF; ROHS: Yes
J4 = CONN_HDR_6X2: CON 2X6 SKT TH 100MIL CTR 345H AU 126L; AGILE_PN: 210-80189; ASSY_OPT: DNP; CAD_APPROVED: Yes; FPLIST: hdr_2x6_2p54_th,hdr_2x6_2p54_th_nsp; HEIGHT: 8.75MM; MFG_NAME01: ANYTRONIC CORPORATION LIMITED; MFG_PN01: 08010S31211-24LF; ROHS: Yes
J15 = CONN_HDR_3X1: HDR 1X3 TH 100MIL SP 330H AU 98L; AGILE_PN: 210-75442; ASSY_OPT: DNP; CAD_APPROVED: Yes; HEIGHT: 8.38 MM; MFG_NAME01: SAMTEC; MFG_PN01: HTSW-103-07-S-S; ROHS: Yes
Q1 = PT12_PHTRANS_2P: TRAN NPN PHOTO 2.5-5.5V 630NM SMT; AGILE_PN: 480-78363; CAD_APPROVED: Yes; HEIGHT: 0.7MM; MFG_NAME01: EVERLIGHT INTERNATIONAL CORPORATION; ROHS: Yes
R1 = RES: RES MF 10.0 OHM 1/10W 1% 0603; AGILE_PN: 470-75423; CAD_APPROVED: Yes; FPLIST: RC0603_OV,RC0603,0603_CC; MFG_NAME01: KOA SPEER; MFG_PN01: RK73H1JTTD10R0F; ROHS: Yes; Tolerance: 1%
R36 R43-R45 = RES: RES MF 10K 1/10W 5% 0603; AGILE_PN: 470-75410; ASSY_OPT: DNP; CAD_APPROVED: Yes; FPLIST: RC0603_OV,RC0603,0603_CC; MFG_NAME01: KOA SPEER; MFG_PN01: RK73B1JTTD103J; ROHS: Yes; Tolerance: 5%
R51 R52 = RES: RES MF ZERO OHM 1/10W -- 0603; AGILE_PN: 470-75407; ASSY_OPT: DNP; CAD_APPROVED: Yes; FPLIST: RC0603_OV,RC0603,0603_CC; MFG_NAME01: VISHAY INTERTECHNOLOGY; MFG_PN01: CRCW06030000Z0EA; ROHS: Yes; Tolerance: 1%
U1 = LD1117AS18: IC VREG LDO 1A 3.3V SOT223; AGILE_PN: 312-80039; CAD_APPROVED: Yes; HEIGHT: 1.8MM; MFG_NAME01: ON Semiconductor; ROHS: Yes
U2 = MAG3112_DFN_10P: IC 3-AXIS DIGITAL MAGNETOMETER 1.95-3.6V DFN10; AGILE_PN: 312-79970; CAD_APPROVED: Yes; FPLIST: DFN_10_0P4_2X2,DFN_10_0P4_2X2_A,DFN_10_0P4_2X2_B; HEIGHT: 0.9MM; MFG_NAME01: FREESCALE SEMICONDUCTOR; MFG_PN01: MAG3110FC; ROHS: Yes
U10 = MMA8451Q_16P_A: IC 3-AXIS DIG ACCELEROMETER 14/8BIT 1.95-3.6V QFN16; AGILE_PN: 315-79075; CAD_APPROVED: Yes; HEIGHT: 1MM; MFG_NAME01: FREESCALE SEMICONDUCTOR; MFG_PN01: MMA8451QT; ROHS: Yes

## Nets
GND: BT1.3(neg) C1.2 C2.2 C3.2 C4.2 C5.2 C6.2 C7.2 C8.2 C9.2 C10.2 C11.2 C12.1 C14.2 C15.1 C16.2 C17.2 C18.2 C19.2 C20.2 C21.2 C22.2 C23.2 C24.2 C25.2 C26.2 C27.2 C28.2 C29.2 C30.2 C31.2 C32.2 C33.2 C34.2 C35.2 C36.2 C37.2 C38.2 C39.2 D6.A(ANODE) J2.14 J3.12(B6) J3.14(B7) J10.5(P5) J11.3(A2) J11.5(A3) J13.5(P5) J14.3(A2) J14.5(A3) J15.2 L1.2 L3.2 Q1.2(EMITTER) R16.1 R25.2 R36.2 R37.2 R46.2 R49.2 R51.2 SW1.1(S1) SW2.2(NC) SW3.1(S1) TP1.1(Pin1) TP4.1(Pin1) TP7.1(Pin1) TP27.1(Pin1) U1.1(GND) U2.5(GND1) U2.10(GND2) U3.3(COM_ANODE) U4.9(VSS1) U4.24(VREFL) U4.25(VSSA) U4.29(VSS2) U4.49(VSS3) U4.74(VSS4) U5.7(GND) U6.7(GND) U7.2(VSS1) U7.8(VSSA) U7.33(EPAD) U9.3(COM_ANODE) U10.5(GND1) U10.12(GND3) U10.13(NC13) Y1.2(GND1) Y1.4(GND2) Y2.2(GND1) Y2.4(GND2)
P3V3: C5.1 C25.1 C29.1 C33.1 C38.1 C39.1 D1.C D4.C J3.4(B2) J3.8(B4) J6.2 J9.1 J17.1 R1.2 R2.2 R3.1 R4.2 R6.1 R9.1 R14.1 R19.1 R27.1 R34.1 R43.1 R44.1 R45.1 U2.2(VDD) U2.8(VDDIO) U10.1(VDDIO) U10.14(VDD)
P3V3_BATT: BT1.1(pos1) BT1.2(pos2) C3.1 D1.A TP6.1(Pin1)
P3V3_KL46Z: C7.1 C9.1 C12.2 C18.1 C19.1 C22.1 C23.1 J11.1(A1) J12.2 J17.2 R1.1 R2.1 R17.2 R18.2 TP23.1(Pin1) U4.8(VDD1) U4.22(VDDA) U4.30(VDD2) U4.48(VDD3)
P3V3_SDA: C24.1 J9.2 J14.1(A1) R4.1 R28.1 R33.2 R38.1 R39.1 U5.4(~{OE2}) U5.14(VCC) U6.5(WP_B) U6.6(VCC) U7.1(VDD1) U7.7(VDDA)
P3V3_VREG: C2.1 D4.A J6.1 TP8.1(Pin1) U1.2(VOUT) U1.4(TAB)
P5V0_SDA_USB_CONN_VBUS: J13.1(P1) L4.1
P5V_KL46_USB: J10.1(P1) L2.1
P5V_KL46Z: D2.A D10.A J7.1 J16.2 L2.2 TP5.1(Pin1)
P5V_SDA: C20.1 D3.A D9.A J16.1 L4.2 R26.1 R35.1 U7.6(VREGIN)
P5V_USB: C37.1 D9.C D10.C J3.10(B5) J15.3
A0: J4.2(B1) U4.53(PTB0/LLWU_P5/LCD_P0/ADC0_SE8/TSI0_CH0/I2C0_SCL/TPM1_CH0)
A1: J4.4(B2) U4.54(PTB1/LCD_P1/ADC0_SE9/TSI0_CH6/I2C0_SDA/TPM1_CH1)
A2: J4.6(B3) U4.55(PTB2/LCD_P2/ADC0_SE12/TSI0_CH7/I2C0_SCL/TPM2_CH0)
A3: J4.8(B4) U4.56(PTB3/LCD_P3/ADC0_SE13/TSI0_CH8/I2C0_SDA/TPM2_CH1)
A4: J4.10(B5) U4.72(PTC2/LCD_P22/ADC0_SE11/TSI0_CH15/I2C1_SDA/TPM0_CH1/I2S0_TX_FS)
A5: J4.12(B6) R24.1 U4.71(PTC1/LLWU_P6/RTC_CLKIN/LCD_P21/ADC0_SE15/TSI0_CH14/I2C1_SCL/TPM0_CH0/I2S0_TXD0)
a-A0b: J4.1(A1) U4.18(PTE20/LCD_P59/ADC0_DP0/ADC0_SE0/TPM1_CH0/UART0_TX)
a-A1b: J4.3(A2) U4.19(PTE21/LCD_P60/ADC0_DM0/ADC0_SE4A/TPM1_CH1/UART0_RX)
a-A2b: J4.5(A3) R40.1 U4.20(PTE22/ADC0_DP3/ADC0_SE3/TPM2_CH0/UART2_TX)
a-A3b: J4.7(A4) U4.21(PTE23/ADC0_DM3/ADC0_SE7A/TPM2_CH1/UART2_RX)
a-A4b: J4.9(A5) U4.66(PTB20/LCD_P16/CMP0_OUT)
a-A5b: J4.11(A6) U4.27(PTE30/DAC0_OUT/ADC0_SE23/CMP0_IN4/TPM0_CH3/TPM_CLKIN1)
a-d0b: J1.1(A1) U4.64(PTB18/LCD_P14/TSI0_CH11/TPM2_CH0/I2S0_TX_BCLK)
a-d1b: J1.3(A2) U4.65(PTB19/LCD_P15/TSI0_CH12/TPM2_CH1/I2S0_TX_FS)
a-d2b: J1.5(A3) U4.70(PTC0/LCD_P20/ADC0_SE14/TSI0_CH13/EXTRG_IN/AUDIOUSB_SOF_OUT/CMP0_OUT/I2S0_TXD0)
a-d3b: J1.7(A4) U4.80(PTC4/LLWU_P8/LCD_P24/SPI0_PCS0/UART1_TX/TPM0_CH3/I2S0_MCLK)
a-d4b: J1.9(A5) U4.82(PTC6/LLWU_P10/LCD_P26/CMP0_IN0/SPI0_MOSI/EXTRG_IN/I2S0_RX_BCLK/SPI0_MISO/I2S0_MCLK)
a-d5b: J1.11(A6) U4.83(PTC7/LCD_P27/CMP0_IN1/SPI0_MISO/AUDIOUSB_SOF_OUT/I2S0_RX_FS/SPI0_MOSI)
a-d6b: J1.13(A7) U4.86(PTC10/LCD_P30/I2C1_SCL/I2S0_RX_FS)
a-d7b: J1.15(A8) U4.87(PTC11/LCD_P31/I2C1_SDA/I2S0_RXD0)
AREF: J2.16 R13.2
CAP_A: C10.1 U2.1(CAP_A)
CAP_R: C6.1 U2.4(CAP_R)
CRST: C8.1 U10.8(NC8)
D0: J1.2(B1) R47.1 U4.35(PTA1/TSI0_CH2/UART0_RX/TPM2_CH0)
D1: J1.4(B2) R48.1 U4.36(PTA2/TSI0_CH3/UART0_TX/TPM2_CH1)
D2: J1.6(B3) U4.96(PTD3/LCD_P43/SPI0_MISO/UART2_TX/TPM0_CH3/SPI0_MOSI)
D3: J1.8(B4) U4.42(PTA12/TPM1_CH0/I2S0_TXD0)
D4: J1.10(B5) U4.38(PTA4/~{NMI}/TSI0_CH5/I2C1_SDA/TPM0_CH1)
D5: J1.12(B6) U4.39(PTA5/USB_CLKIN/TPM0_CH2/I2S0_TX_BCLK)
D6: J1.14(B7) U4.84(PTC8/LCD_P28/CMP0_IN2/I2C0_SCL/TPM0_CH4/I2S0_MCLK)
D7: J1.16(B8) U4.85(PTC9/LCD_P29/CMP0_IN3/I2C0_SDA/TPM0_CH5/I2S0_RX_BCLK)
D8: J2.2 U4.43(PTA13/TPM1_CH1/I2S0_TX_FS)
D9: J2.4 U4.95(PTD2/LCD_P42/SPI0_MOSI/UART2_RX/TPM0_CH2/SPI0_MISO)
D10: J2.6 U4.97(PTD4/LLWU_P14/LCD_P44/SPI1_PCS0/UART2_RX/TPM0_CH4)
D11: J2.8 U4.99(PTD6/LLWU_P15/LCD_P46/ADC0_SE7B/SPI1_MOSI/UART0_RX/SPI1_MISO)
D12: J2.10 U4.100(PTD7/LCD_P47/SPI1_MISO/UART0_TX/SPI1_MOSI)
D13: J2.12 R11.1 U4.98(PTD5/LCD_P45/ADC0_SE6B/SPI1_SCK/UART2_TX/TPM0_CH5)
D14: J2.18 U4.1(PTE0/LCD_P48/SPI1_MISO/UART1_TX/RTC_CLKOUT/CMP0_OUT/I2C1_SDA)
D15: J2.20 U4.2(PTE1/LCD_P49/SPI1_MOSI/UART1_RX/SPI1_MISO/I2C1_SCL)
EXTAL_8MHZ: C28.1 R31.1 U4.50(PTA18/EXTAL0/UART1_RX/TPM_CLKIN0) Y1.1
I2C0_SCL: R9.2 U2.7(SCL) U4.31(PTE24/TPM0_CH0/I2C0_SCL) U10.4(SCL)
I2C0_SDA: R6.2 U2.6(SDA) U4.32(PTE25/TPM0_CH1/I2C0_SDA) U10.6(SDA)
INT1_ACCEL: R20.1 R44.2 U10.11(INT1)
INT1_MAG: R50.1 U2.9(INT1)
INT2_ACCEL: R41.2 R43.2 R50.2 U10.9(INT2)
KL25_SWD_CLK: J18.1 U4.34(PTA0/SWD_CLK/TSI0_CH1/TPM0_CH5)
KL46_USB_DN: J10.2(P2) R10.1 U3.1(CATHODE1)
KL46_USB_DP: J10.3(P3) R8.1 U3.2(CATHODE2)
KL46_USB_ID: J10.4(P4) R16.2 TP9.1(Pin1)
KL46_USB_SHLD: J10.S1(SHLD1) J10.S2(SHLD2) J10.S3(SHLD3) J10.S4(SHLD4) L1.1
KL46Z_REGIN: J7.2 U4.13(VREGIN)
LCD-01: DS1.1(COM0) U4.93(PTD0/LCD_P40/SPI0_PCS0/TPM0_CH0)
LCD-02: DS1.2(COM1) U4.5(PTE4/LCD_P52/SPI1_PCS0)
LCD-03: DS1.3(COM2) U4.69(PTB23/LCD_P19)
LCD-04: DS1.4(COM3) U4.68(PTB22/LCD_P18)
LCD-05: DS1.5(1D/1E/1G/1F) U4.91(PTC17/LCD_P37)
LCD-06: DS1.6(DP1/1C/1B/1A) U4.67(PTB21/LCD_P17)
LCD-07: DS1.7(2D/2E/2G/2F) U4.57(PTB7/LCD_P7)
LCD-08: DS1.8(DP2/2C/2B/2A) U4.58(PTB8/LCD_P8/SPI1_PCS0/EXTRG_IN)
LCD-09: DS1.9(3D/3E/3G/3F) U4.6(PTE5/LCD_P53)
LCD-10: DS1.10(DP3/3C/3B/3A) U4.92(PTC18/LCD_P38)
LCD-11: DS1.11(4D/4E/4G/4F) U4.60(PTB10/LCD_P10/SPI1_PCS0)
LCD-12: DS1.12(COL/4C/4B/4A) U4.61(PTB11/LCD_P11/SPI1_SCK)
LED1: D7.C(CATHODE) R11.2
LED2: D5.C(CATHODE) U4.26(PTE29/CMP0_IN5/ADC0_SE4B/TPM0_CH2/TPM_CLKIN0)
Light_sns: J8.1 R40.2
P5-9V_VIN: C4.1 C34.1 C35.1 C36.1 D2.C D3.C J3.16(B8) J15.1 U1.3(VIN)
PTA6: J2.7 U4.40(PTA6/TPM0_CH3)
PTA7: J2.5 U4.41(PTA7/TPM0_CH4)
PTA14: J2.9 U4.44(PTA14/SPI0_PCS0/UART0_TX/I2S0_RX_BCLK/I2S0_TXD0)
PTA15: J2.11 U4.45(PTA15/SPI0_SCK/UART0_RX/I2S0_RXD0)
PTA16: J2.13 U4.46(PTA16/SPI0_MOSI/SPI0_MISO/I2S0_RX_FS/I2S0_RXD0)
PTA17: J2.15 U4.47(PTA17/SPI0_MISO/SPI0_MOSI/I2S0_MCLK)
PTB9: J2.17 U4.59(PTB9/LCD_P9/SPI1_SCK)
PTC1_SDA: R24.2 U7.31(ADC0_SE7B/PTD6/SPI0_PCS3/UART0_RX/FTM0_CH6/FTM0_FLT0/LLWU_P15)
PTC13: J2.1 U4.89(PTC13/LCD_P33/TPM_CLKIN1)
PTC16: J2.3 U4.90(PTC16/LCD_P36)
PTE2: J3.15(A8) U4.3(PTE2/LCD_P50/SPI1_SCK)
PTE3: J3.13(A7) U4.4(PTE3/LCD_P51/SPI1_MISO/SPI1_MOSI)
PTE6: J3.11(A6) U4.7(PTE6/LCD_P54/I2S0_MCLK/AUDIOUSB_SOF_OUT)
PTE16: J3.9(A5) U4.14(PTE16/LCD_P55/ADC0_DP1/ADC0_SE1/SPI0_PCS0/UART2_TX/TPM_CLKIN0)
PTE17: J3.7(A4) U4.15(PTE17/LCD_P56/ADC0_DM1/ADC0_SE5A/SPI0_SCK/UART2_RX/TPM_CLKIN1/LPTMR0_ALT3)
PTE18: J3.5(A3) U4.16(PTE18/LCD_P57/ADC0_DP2/ADC0_SE2/SPI0_MOSI/I2C0_SDA/SPI0_MISO)
PTE19: J3.3(A2) U4.17(PTE19/LCD_P58/ADC0_DM2/ADC0_SE6A/SPI0_MISO/I2C0_SCL/SPI0_MOSI)
PTE26: R52.2 TP30.1(Pin1) U4.33(PTE26/TPM0_CH5/RTC_CLKOUT/USB_CLKIN)
PTE31: J3.1(A1) U4.28(PTE31/TPM0_CH4)
RST_K20D50_B: C17.1 J3.6(B3) J11.10(B5) R19.2 SW2.1(COMMON) U4.52(PTA20/~{RESET}) U7.21(ADC0_SE9/TSI0_CH6/PTB1/I2C0_SDA/FTM1_CH1/FTM1_QD_PHB)
SDA_EXTAL: C31.1 U7.17(EXTAL0/PTA18/FTM0_FLT2/FTM_CLKIN0) Y2.3
SDA_JTAG_TCLK: J14.4(B2) U7.12(JTAG_TCLK/SWD_CLK/EZP_CLK/TSI0_CH1/PTA0/~{UART0_CTS}/~{UART0_COL}/FTM0_CH5)
SDA_JTAG_TDI: J14.8(B4) U7.13(JTAG_TDI/EZP_DI/TSI0_CH2/PTA1/UART0_RX/FTM0_CH6)
SDA_JTAG_TDO: J14.6(B3) U7.14(JTAG_TDO/TRACE_SWO/EZP_DO/TSI0_CH3/PTA2/UART0_TX/FTM0_CH7)
SDA_JTAG_TMS: J14.2(B1) R38.2 U7.15(JTAG_TMS/SWD_DIO/TSI0_CH4/PTA3/~{UART0_RTS}/FTM0_CH0)
SDA_LED: D8.C(CATHODE) TP22.1(Pin1) U7.29(PTD4/SPI0_PCS1/~{UART0_RTS}/FTM0_CH4/EWM_IN/LLWU_P14)
SDA_LED_R: D8.A(ANODE) R28.2
SDA_PTD5: J3.2(B1) U7.30(ADC0_SE6B/PTD5/SPI0_PCS2/~{UART0_CTS}/~{UART0_COL}/FTM0_CH5/~{EWM_OUT})
SDA_RST_B: J14.10(B5) R35.2 R37.1 TP28.1(Pin1) U7.19(~{RESET})
SDA_SPI0_CS: TP16.1(Pin1) U6.4(CS_B) U7.23(ADC0_SE4B/CMP1_IN0/TSI0_CH15/PTC2/SPI0_PCS2/~{UART1_CTS}/FTM0_CH1/I2S0_TX_FS)
SDA_SPI0_RST_B: TP17.1(Pin1) U6.3(RSET_B) U7.22(ADC0_SE15/TSI0_CH14/PTC1/SPI0_PCS3/~{UART1_RTS}/FTM0_CH0/I2S0_TXD0/LLWU_P6)
SDA_SPI0_SCK: TP18.1(Pin1) U5.12(4A) U6.2(SCK) U7.26(PTC5/SPI0_SCK/LPTMR0_ALT2/I2S0_RXD0/CMP0_OUT/LLWU_P9)
SDA_SPI0_SIN: TP13.1(Pin1) U5.8(3Y) U6.8(SO) U7.28(CMP0_IN1/PTC7/SPI0_SIN/USB_SOF_OUT/I2S0_RX_FS)
SDA_SPI0_SOUT: TP19.1(Pin1) U5.2(1A) U6.1(SI) U7.27(CMP0_IN0/PTC6/SPI0_SOUT/PDB0_EXTRG/I2S0_RX_BCLK/I2S0_MCLK/LLWU_P10)
SDA_SWD_EN: R39.2 U5.10(~{OE3}) U5.13(~{OE4}) U7.16(~{NMI}/~{EZP_CS}/TSI0_CH5/PTA4/FTM0_CH1/LLWU_P3)
SDA_SWD_OE_B: R33.1 U5.1(~{OE1}) U7.20(ADC0_SE8/TSI0_CH0/PTB0/I2C0_SCL/FTM1_CH0/FTM1_QD_PHA/LLWU_P5)
SDA_USB_CONN_DN: J13.2(P2) R30.1 U9.1(CATHODE1)
SDA_USB_CONN_DP: J13.3(P3) R29.1 U9.2(CATHODE2)
SDA_USB_DN: R30.2 U7.4(USB0_DM)
SDA_USB_DP: R29.2 U7.3(USB0_DP)
SDA_USB_P5V_SENSE: R25.1 R26.2 TP21.1(Pin1) U7.32(PTD7/CMT_IRO/UART0_TX/FTM0_CH7/FTM0_FLT1)
SDA_USB_VOUT33: C27.1 U7.5(VOUT33)
SDA_USBSHIELD: J13.S1(SHLD1) J13.S2(SHLD2) J13.S3(SHLD3) J13.S4(SHLD4) L3.1
SDA_XTAL: C30.1 U7.18(XTAL0/PTA19/FTM1_FLT0/FTM_CLKIN1/LPTMR0_ALT1) Y2.1
SNS_LIGHT_ADC: J8.2 Q1.1(COLLECTOR) R3.2
SNSR_BYP: C21.1 TP20.1(Pin1) U10.2(BYP)
SNSR_I2C_SA0: R34.2 R36.1 TP26.1(Pin1) U10.7(SA0)
SNSR_I2C_SA1: R45.2 R46.1 TP29.1(Pin1) U10.10(GND2)
SW1: C1.1 SW1.2(S2) U4.73(PTC3/LLWU_P7/LCD_P23/UART1_RX/TPM0_CH2/CLKOUT/I2S0_TX_BCLK)
SW2: C32.1 SW3.2(S2) U4.88(PTC12/LCD_P32/TPM_CLKIN0)
SWD_CLK_TGTMCU: J11.4(B2) J18.2 U5.11(4Y)
SWD_DIO_TGTMCU: J11.2(B1) U4.37(PTA3/SWD_DIO/TSI0_CH4/I2C1_SCL/TPM0_CH0) U5.3(1Y) U5.9(3A)
TC_74125_SPARE_I_TP: R49.1 TP14.1(Pin1) U5.5(2A)
TC_74125_SPARE_O_TP: TP15.1(Pin1) U5.6(2Y)
TC_EXTAL_TP: TP2.1(Pin1) U7.10(EXTAL32)
TC_SDA_USB_ID_TP: J13.4(P4) TP24.1(Pin1)
TC_VBAT_TP: TP25.1(Pin1) U7.11(VBAT)
TC_XTAL_TP: TP3.1(Pin1) U7.9(XTAL32)
TSI_ELECTRODE1: E1.1 U4.62(PTB16/LCD_P12/TSI0_CH9/SPI1_MOSI/UART0_RX/TPM_CLKIN0/SPI1_MISO)
TSI_ELECTRODE2: E1.2 U4.63(PTB17/LCD_P13/TSI0_CH10/SPI1_MISO/UART0_TX/TPM_CLKIN1/SPI1_MOSI)
UART1_RX_TGTMCU: R47.2 U7.25(PTC4/SPI0_PCS0/UART1_TX/FTM0_CH3/CMP1_OUT/LLWU_P8)
UART1_TX_TGTMCU: R48.2 U7.24(CMP1_IN1/PTC3/SPI0_PCS1/UART1_RX/FTM0_CH2/I2S0_TX_BCLK/LLWU_P7)
USB_DM: R10.2 U4.11(USB0_DM)
USB_DP: R8.2 U4.10(USB0_DP)
VCAP1: C13.1 U4.79(VCAP1/LCD_P39/PTC23)
VCAP2: C13.2 U4.78(VCAP2/LCD_P6/PTC22)
VLL1: C14.1 TP10.1(Pin1) U4.77(VLL1/LCD_P5/PTC21)
VLL2: C16.1 TP12.1(Pin1) U4.76(VLL2/LCD_P4/PTC20)
VLL3: J12.1 U4.75(VLL3)
VOUT33: C11.1 TP11.1(Pin1) U4.12(VOUT33)
VREFH: C15.2 D6.C(CATHODE) R13.1 R17.1 R18.1 U4.23(VREFH)
XTAL_8MHZ: C26.1 R31.2 U4.51(PTA19/XTAL0/UART1_TX/TPM_CLKIN1/LPTMR0_ALT1) Y1.3
N20481384: D7.A(ANODE) R27.2
N20482076: D5.A(ANODE) R14.2
N20556368: R41.1 U4.94(PTD1/LCD_P41/ADC0_SE5B/SPI0_SCK/TPM0_CH1)
N20556470: R20.2 U4.81(PTC5/LLWU_P9/LCD_P25/SPI0_SCK/LPTMR0_ALT2/I2S0_RXD0/CMP0_OUT)
N20638389: R51.1 U10.3(NC3)
N20639261: R52.1 U10.16(NC16)

Not connected (* = marked no-connect by the designer): J2 19*; J11 6(B3)* 7(A4)* 8(B4)* 9(A5)*; J14 7(A4)* 9(A5)*; U2 3(NC)*; U10 15(NC15)*

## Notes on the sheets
sheet 1
- Table of Contents
- Revisions
- 1
- Title
- Rev
- Description
- Date
- Approved
- 2
- Block Diagram
- A
- Initial version
- 3
- KL46Z MCU
- 4
- OpenSDA INTERFACE
- 1. As per the new FRDM-KL46 pin assignment xls
  connections changed.
  2. Net changed from SWD_CLKto
  SWD_CLK_TGTMCU in connector J11.2
  3. Net name TSI0_CH9/TSI0_CH10 removed from
  touch interface.
  4. Port name and Arduino functions name Text
  added to the nets.
  5. 5V regulator PAD added
  6. separate Accelarometer and Magnetometer
  sensor Freplaced with FXOS8700CQ
  7. PPL Released
- 5
- I/O Headers and Power Supply
- Luis
  Puebla
  Palma
- AX1
- 07-MAR-13
- 1. As per the FRDM-KL46 new pinout assignement
   Rev3.xls connections changed.
  2. Port name and Arduino functions name Text
  changed to the nets as per new pin assignment.
  3. Arduino connector Ref des changed as per TRD
  requirement
  4. INT1_MAG net removed
  5. Test point added in PTE26
- AX2
- 14-MAR-13
- Luis
  Puebla
  Palma
- 1. Magnetometer circuit added with same I2C
  Bus (I2C0_SCL/SDA)
  2. Magnetometer interrupt is connected to
  Accelerometer interrupt 2 through a 0 ohms
  resistor.
  3. Spare buffer U5B input is pulled low using a 0
  ohms res.
- Luis
  Puebla
  Palma
- AX3
- 25-MAR-13
- 1. FXOS8700CQ replaced with MMA8451Q. NC
  Pins wired to make compatible with CRST, RST,
  RSVD1/2 in FXOS8700CQ
  2. DNP 0 ohm resistor added between Inertial
  sensor 3rd pin and GND.
  3. DNP 0 ohms resistor added b/w Inertial
  sensor 16th pin and PTE26
- AX4
- Luis
  Puebla
  Palma
- 26-MAR-13
- Luis
  Puebla
  Palma
- B
- 1. DNP Updated
  2. RST_K20D50 renamed to RST_K20D50_B
  3. A085 Release
- 28-MAR-13
- FRDM-KL46Z
- 1. D6 - DNP
  2. J7 - MOUNT
  3. Schematic title changed to  FRDM-KL46Z
  4. A085 Release
- Luis
  Puebla
  Palma
- B1
- 03-MAY-13
sheet 2
- 1. Unless Otherwise Specified:
- All resistors are in ohms, 5%, 1/8 Watt
- All capacitors are in uF, 20%, 50V
- All voltages are DC
- All polarized capacitors are aluminum electrolytic
- 2. Interrupted lines coded with the same letter or letter
      combinations are electrically connected.
- 3. Device type number is for reference only. The number
      varies with the manufacturer.
- 4. Special signal usage:
- _B Denotes - Active-Low Signal
- <> or [] Denotes - Vectored Signals
- 5. Interpret diagram in accordance with American
  National Standards Institute specifications, current
  revision, with the exception of logic block symbology.
sheet 3
- KL46Z Decoupling Caps
- Push Buttons
- PTA1 - D0/RX/int
- PTA2 - D1/TX/int
- PTA4 - D4/int
- PTA5 - D5/PWM/int
- PTA6
- PTA7
- PTA12 - D3/PWM/int
- PTA13 - D8/InputCapture/int
- PTA14
- PTA15
- PTA16
- PTA17
- TSI Capacitive/
  Touch Interface
- PTB0 - A0/Int
- PTB1 - A1/Int
- PTB2 - A2/int
- PTB3 - A3/int
- CAD NOTE:
  Place these capacitors
  near their respective CPU pin
  (VREFH to VREFL
  and VDDA to VSSA)
- PTB9
- PTB18 - I2S_TX_BCLK
- PTB19 - I2S_TX_FS
- PTB20 - CMP_OUT
- PTC0 - I2S_TXD
- PTC1 - A5/SCL/int
- PTC2 - A4/SDA/int
- PTC4 - I2S_MCLK
- PTC6 - I2S_RX_BCLK
- PTC7 - SOF_OUT
- PTC8 - D6/PWM/CMP/int
- SHORTING HEADER ON BOTTOM LAYER
  Jumper is shorted by a cut-trace on
  bottom layer. Cutting the trace
  will effectively isolate the
  on-board MCU from the OpenSDA debug
  interface.
- PTC9 - D7/CMP/int
- PTC10 - I2S_RX_FS
- SWD CONNECTOR
- PTC11 - I2S_RXD
- PTC13
- PTC16
- PTD2 - D9/PWM/int
- PTD3 - D2/int
- PTD4 - D10/SPI_SS/PWM/int
- PTD5 - D13/SCK/LED/int
- PTD6 - D11/MOSI/int
- PTD7 - D12/MISO/int
- PTE0 - D14/SDA/Ana/int
- PTE1 - D15/SCL/Ana/int
- PTE2
- PTE3
- PTE6
- PTE16
- PTE17
- PTE18
- PTE19
- USB
- PTE20 - DIFF_ADC0_DP
- PTE21 - DIFF_ADC0_DM
- PTE22 - DIFF_ADC1_DP
- PTE23 - DIFF_ADC1_DM
- PTE30 - DAC_OUT
- PTE31
- OPTIONAL USB HOST FUNCTIONALITY
- POPULATE THESE PARTS FOR
  USB HOST FUNCTIONALITY
  ELECTRICAL PROTECTION IS
  NOT PROVIDED.
  USE IT AT YOUR OWN RISK
- 7 Segment LCD
- LEDs
sheet 4
- TARGET MCU
  INTERFACE
  SIGNALS
- PU/PD LOGIC:
  SERIAL INTERFACE
  IS ALWAYS RESET
  WHEN USB PORT
  IS DISCONNECTED
- KL46Z Pin
  LCD_P21/ADC0_SE15/TSIO_CH14/PTC1/LLWU_P6/RTC_CLKIN/I2C1_SCLTPM0_CH0/I2S0_TXD0
- OpenSDA INTERFACE
- SPARE 74HC125 buffer
- TARGET RESET AND BOOTLOADER
  PUSH BUTTON
- SPI FLASH MEMORY
- OpenSDA INTERFACE JTAG CONNECTOR
- AT45DB161D-S
           OR
  AT45DB161E-SSHD
sheet 5
- SHORTING HEADER
  ON BOTTOM LAYER
- OPTIONAL COIN CELL HOLDER
- ARDUINO HEADERS
- PTA1 - D0/RX/int
- PTA2 - D1/TX/int
- PTD3 - D2/int
- PTA12 - D3/PWM/int
- PTA4 - D4/int
- PTA5 - D5/PWM/int
- PTC8 - D6/PWM/CMP/int
- PTC9 - D7/CMP/int
- PTA13 - D8/InputCapture/int
- SHORTING HEADER
  ON BOTTOM LAYER
- PTD2 - D9/PWM/int
- PTD4 - D10/SPI_SS/PWM/int
- 20mOhm
  Resistor in
  layout
- PTD6 - D11/MOSI/int
- PTD7 - D12/MISO/int
- PTD5 - D13/SCK/LED/int
- PTE0 - D14/SDA/Ana/int
- PTE1 - D15/SCL/Ana/int
- I2C INERTIAL SENSOR
- I2C Address 0X1D
- PTA17
- PTB9
- PTA16
- PTA15
- PTA14
- PTA6
- PTA7
- PTC16
- PTC13
- PTC11 - I2S_RXD
- PTC10 - I2S_RX_FS
- PTC7 - SOF_OUT
- PTC4 - I2S_MCLK
- PTC6 - I2S_RX_BCLK
- PTC0 - I2S_TXD
- PTB19 - I2S_TX_FS
- *
- PTB18 - I2S_TX_BCLK
- PTE30 - DAC_OUT
- PTB20 - CMP_OUT
- PTE23 - DIFF_ADC1_DM
- PTE22 - DIFF_ADC1_DP
- PTE21 - DIFF_ADC0_DM
- PTE20 - DIFF_ADC0_DP
- **
- PTE2
- PTE3
- PTE6
- NC connections, to make compatible with FXOS8700CQ sensor
  *  Populate these components, if FXOS8700CQ sensor is used
  ** I2C Address config option for FXOS8700CQ
- PTE16
- PTE17
- 5VDC VR
  SUPPORT
- PTE18
- PTE19
- PTE31
- IN
- OUT
- I2C MAGNETOMETER
- VISIBLE LIGHT SENSOR
- I2C Address 0X0E
- IN CIRCUIT TEST
  GND PROBING
- DEBUG
  GND HOOK
- PTB0 - A0/Int
- These comps are DNP, if
  FXOS8700CQ  (Accelerometer
  & magnetometer) sensor is
  used
- PTB1 - A1/Int
- PTB2 - A2/int
- PTB3 - A3/int
- PTC2 - A4/SDA/int
- PTC1 - A5/SCL/int
